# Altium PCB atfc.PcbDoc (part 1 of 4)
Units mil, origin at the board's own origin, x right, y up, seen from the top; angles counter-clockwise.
Board outline 6334.43 x 4147 mil, 6 copper layers (Component Side, Ground Plane (GND), GND/Signal, VCCO/Signal, VCCINT/VCCAUX, Bottom Side), stack 60.473 mil thick; 297 components, 274 nets, 1530 pads, 922 vias.
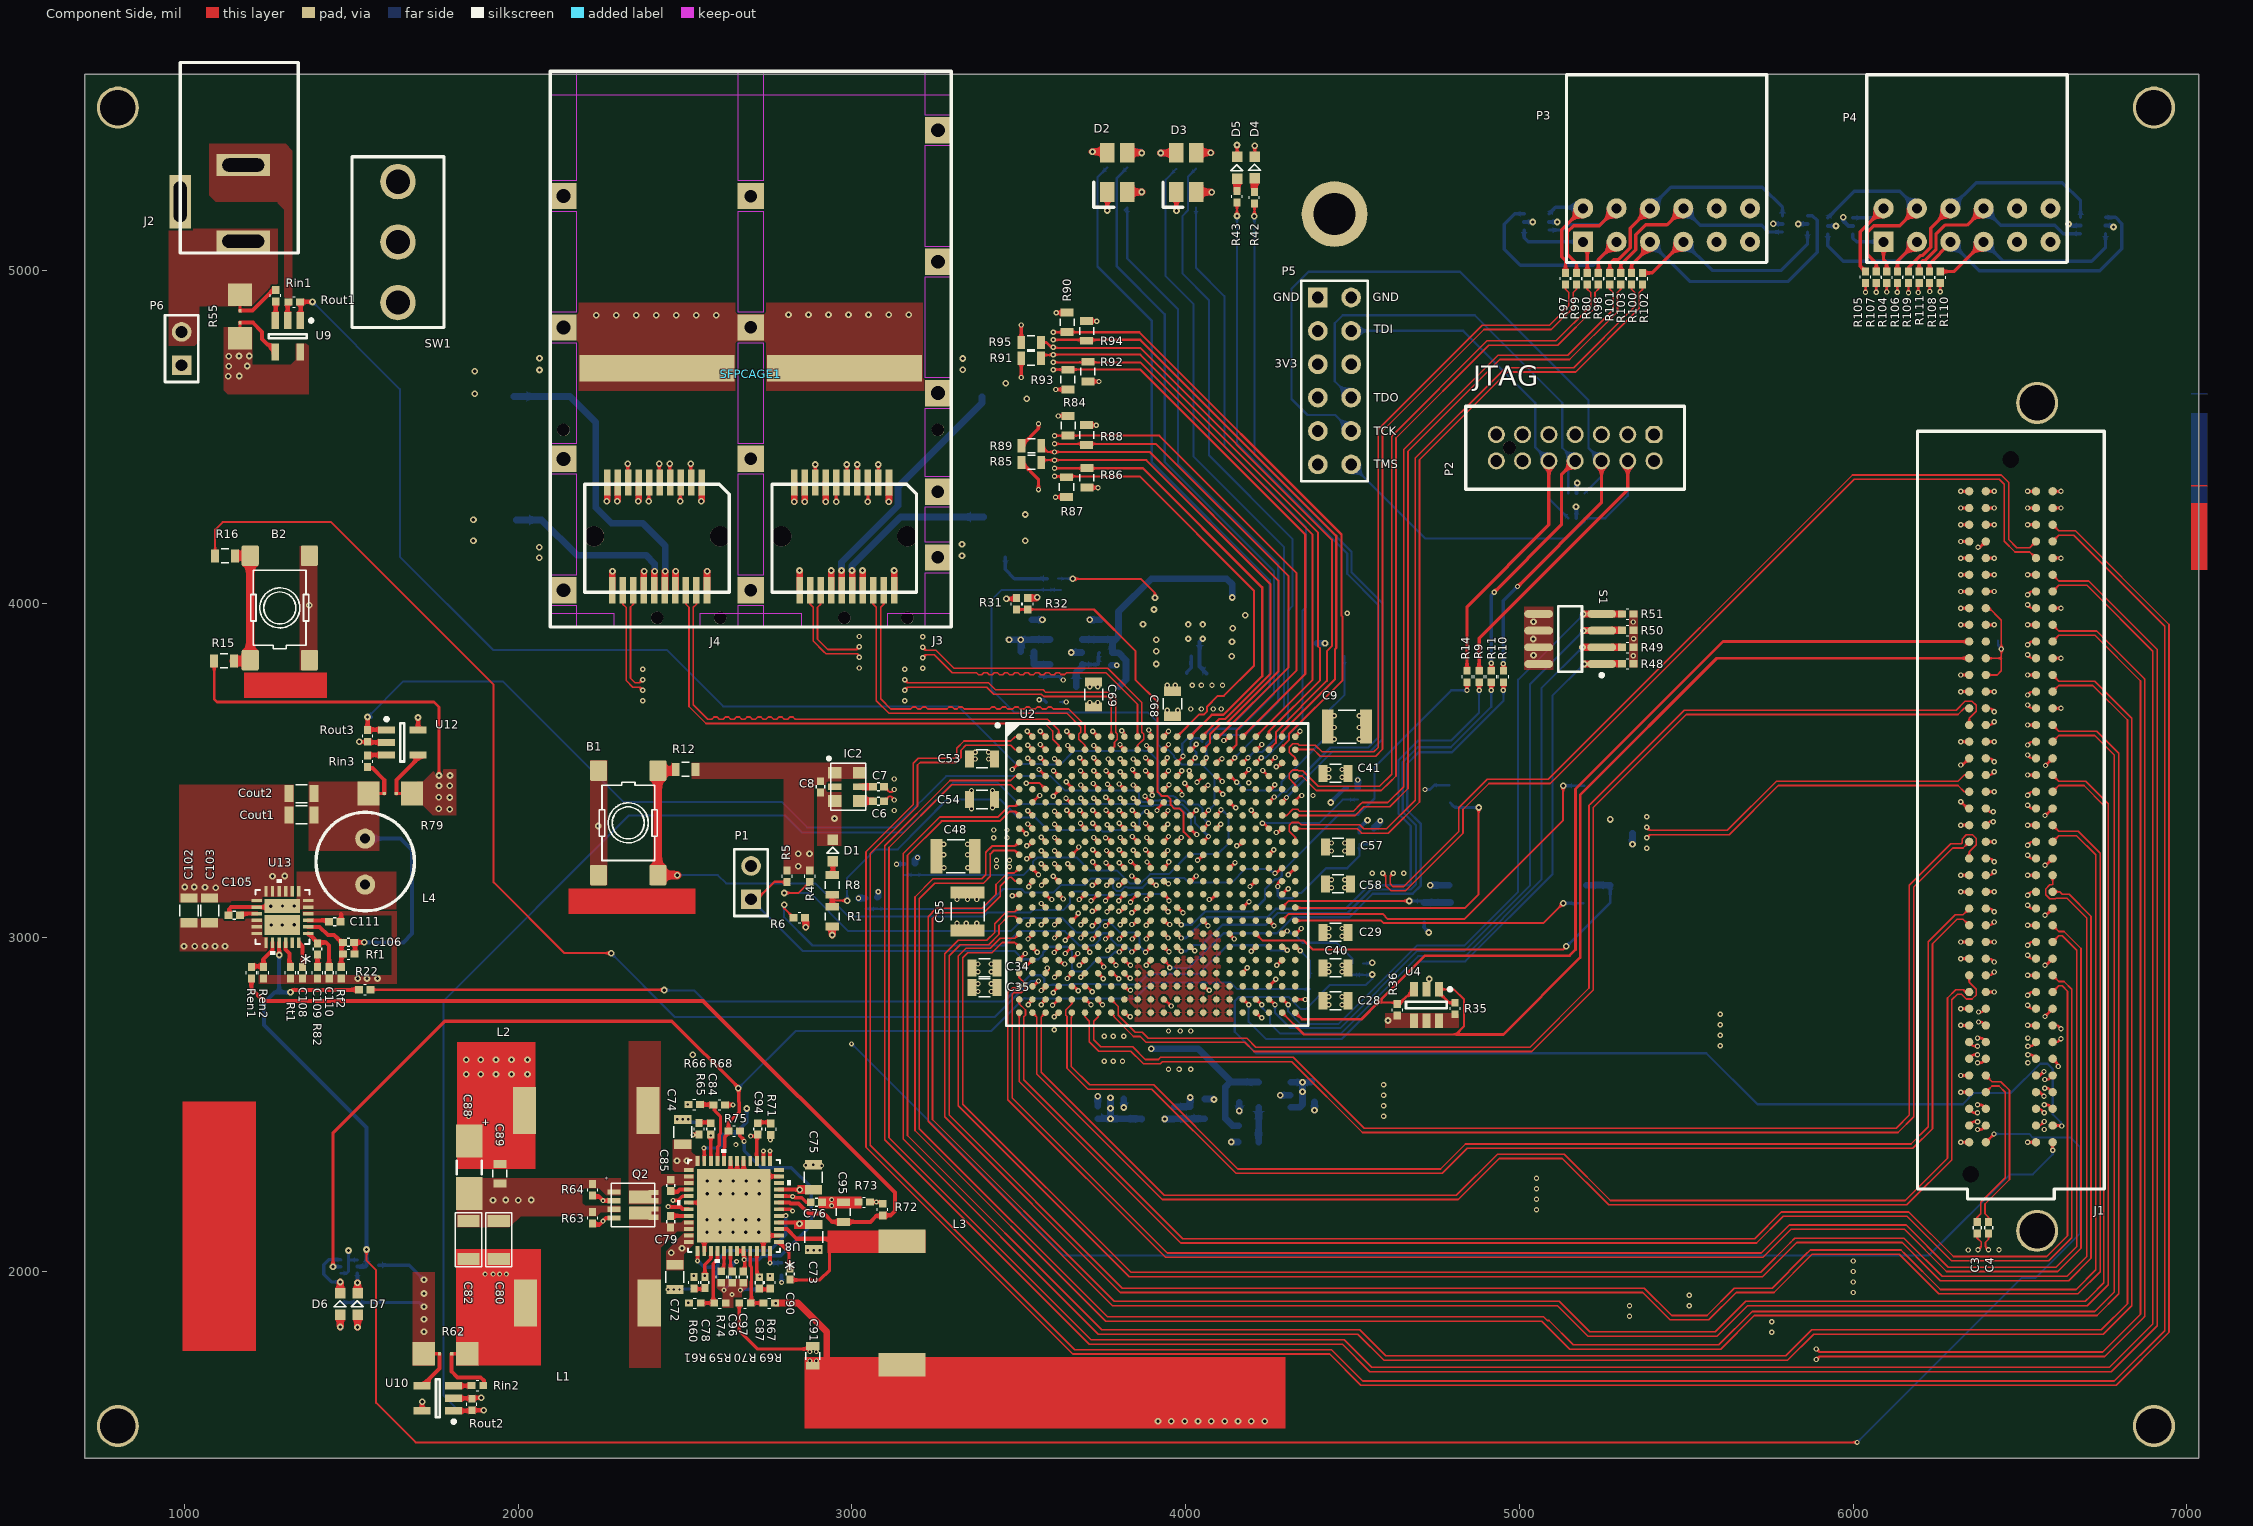
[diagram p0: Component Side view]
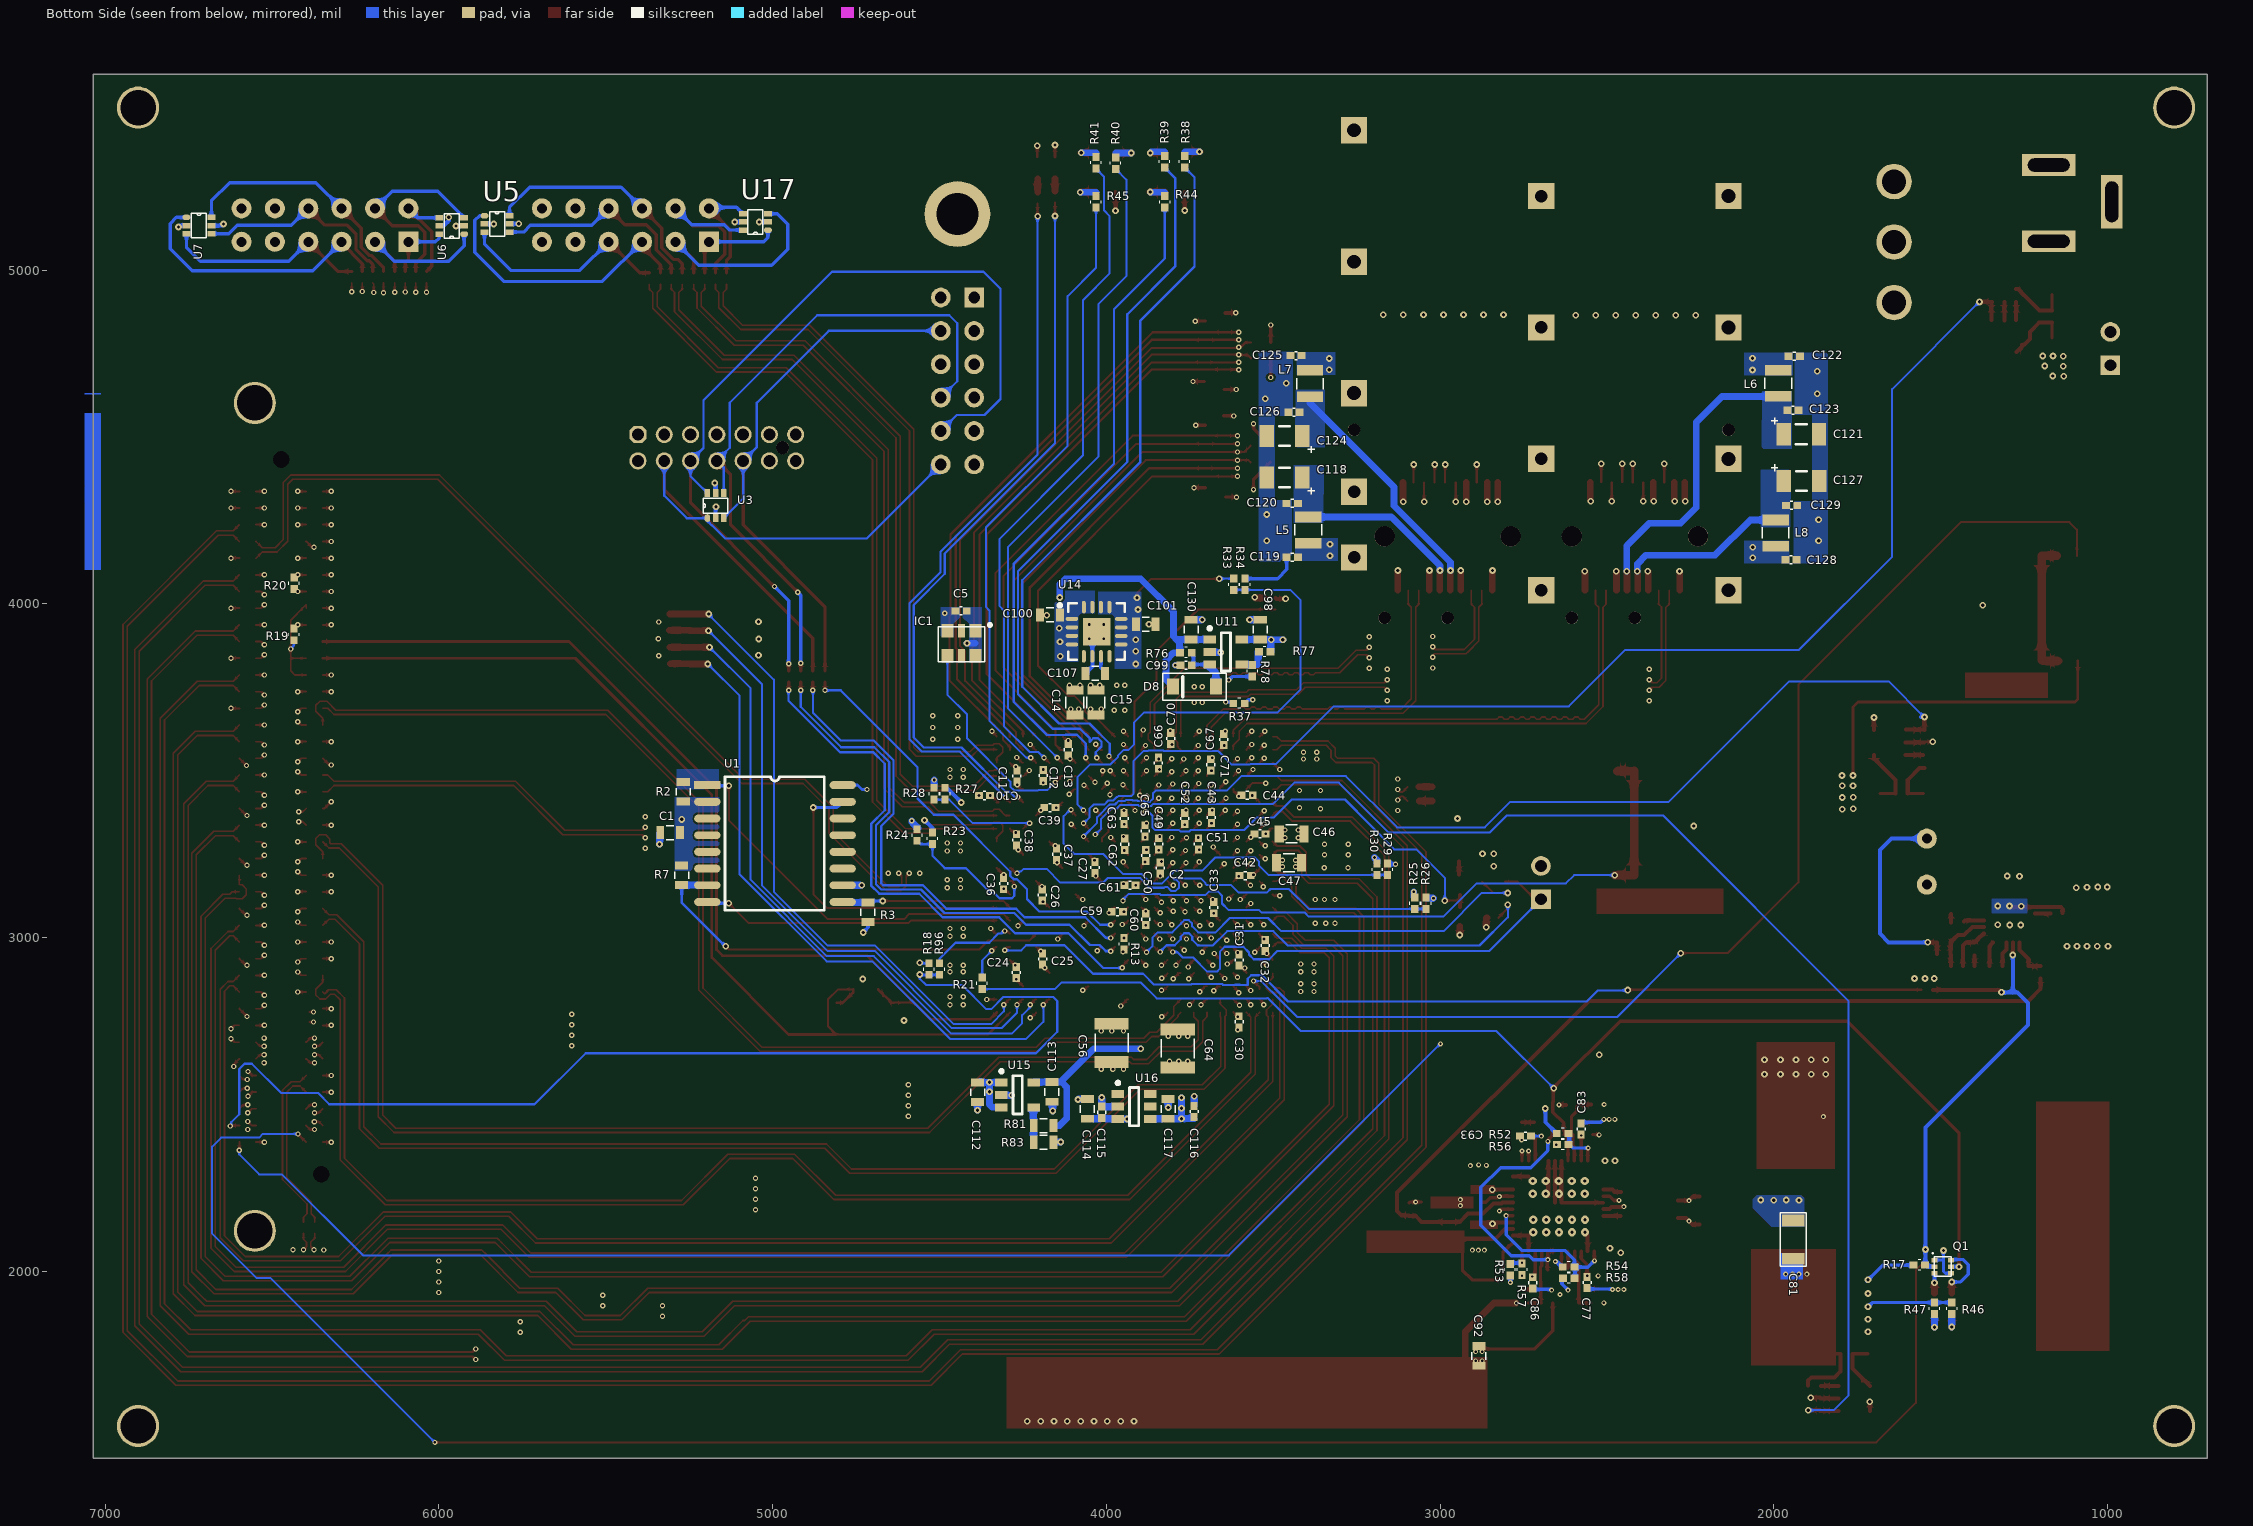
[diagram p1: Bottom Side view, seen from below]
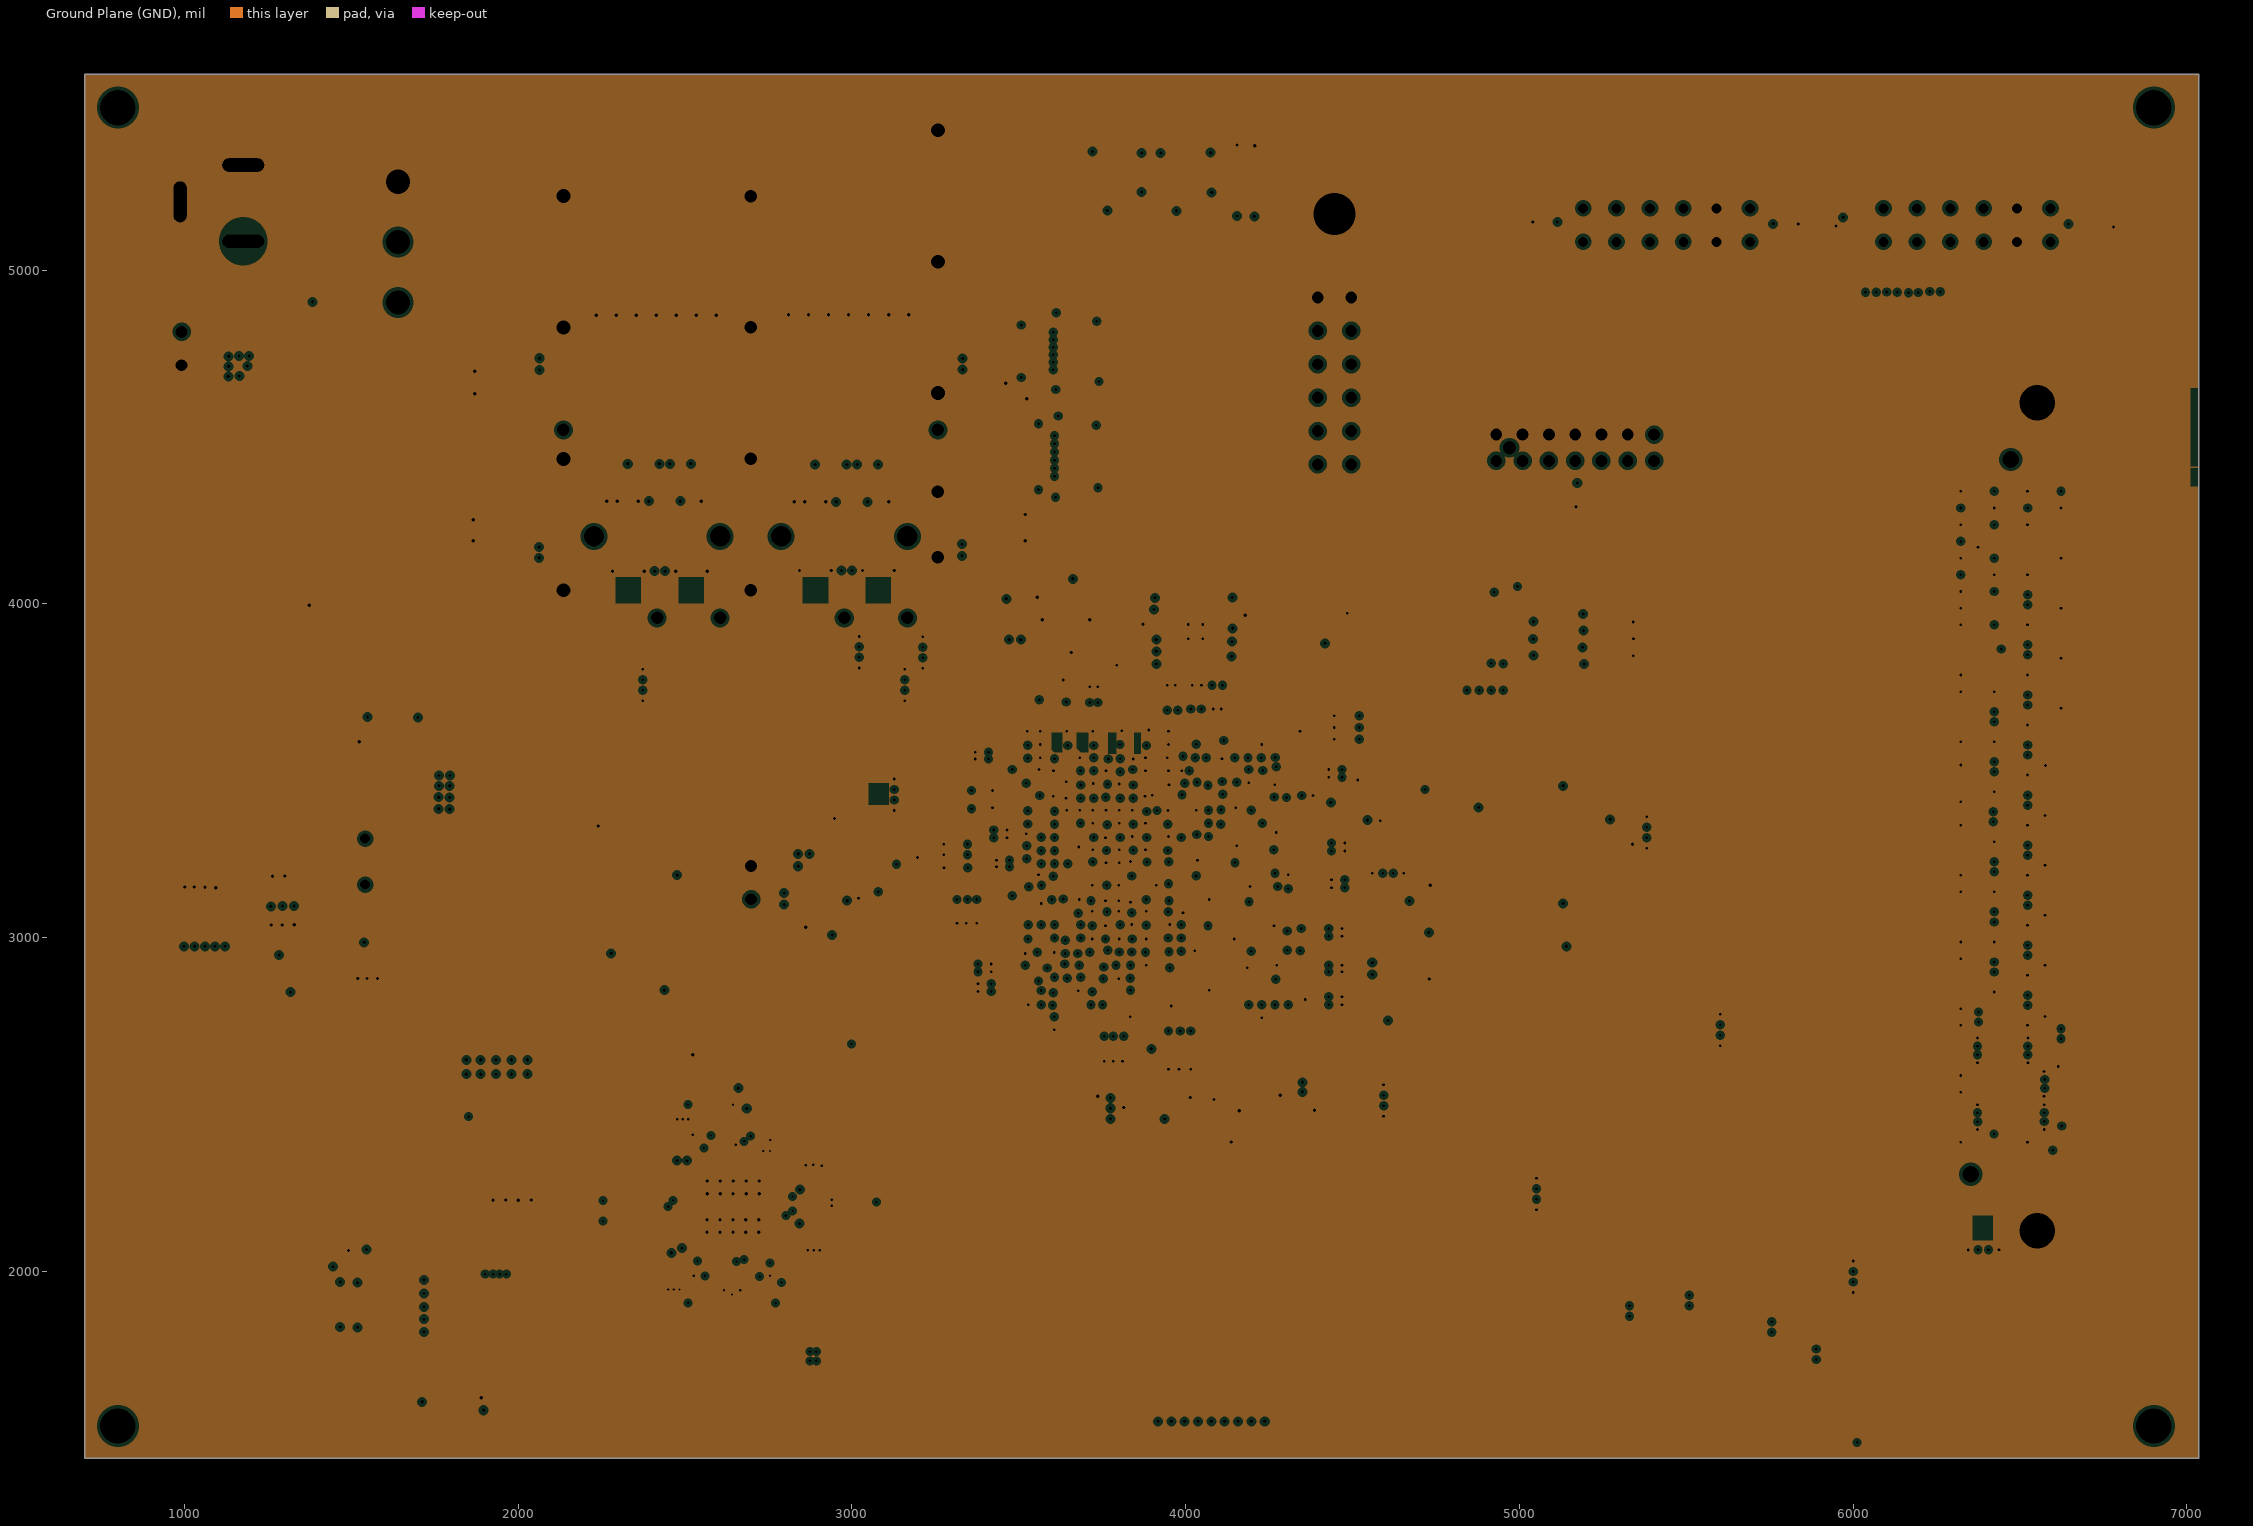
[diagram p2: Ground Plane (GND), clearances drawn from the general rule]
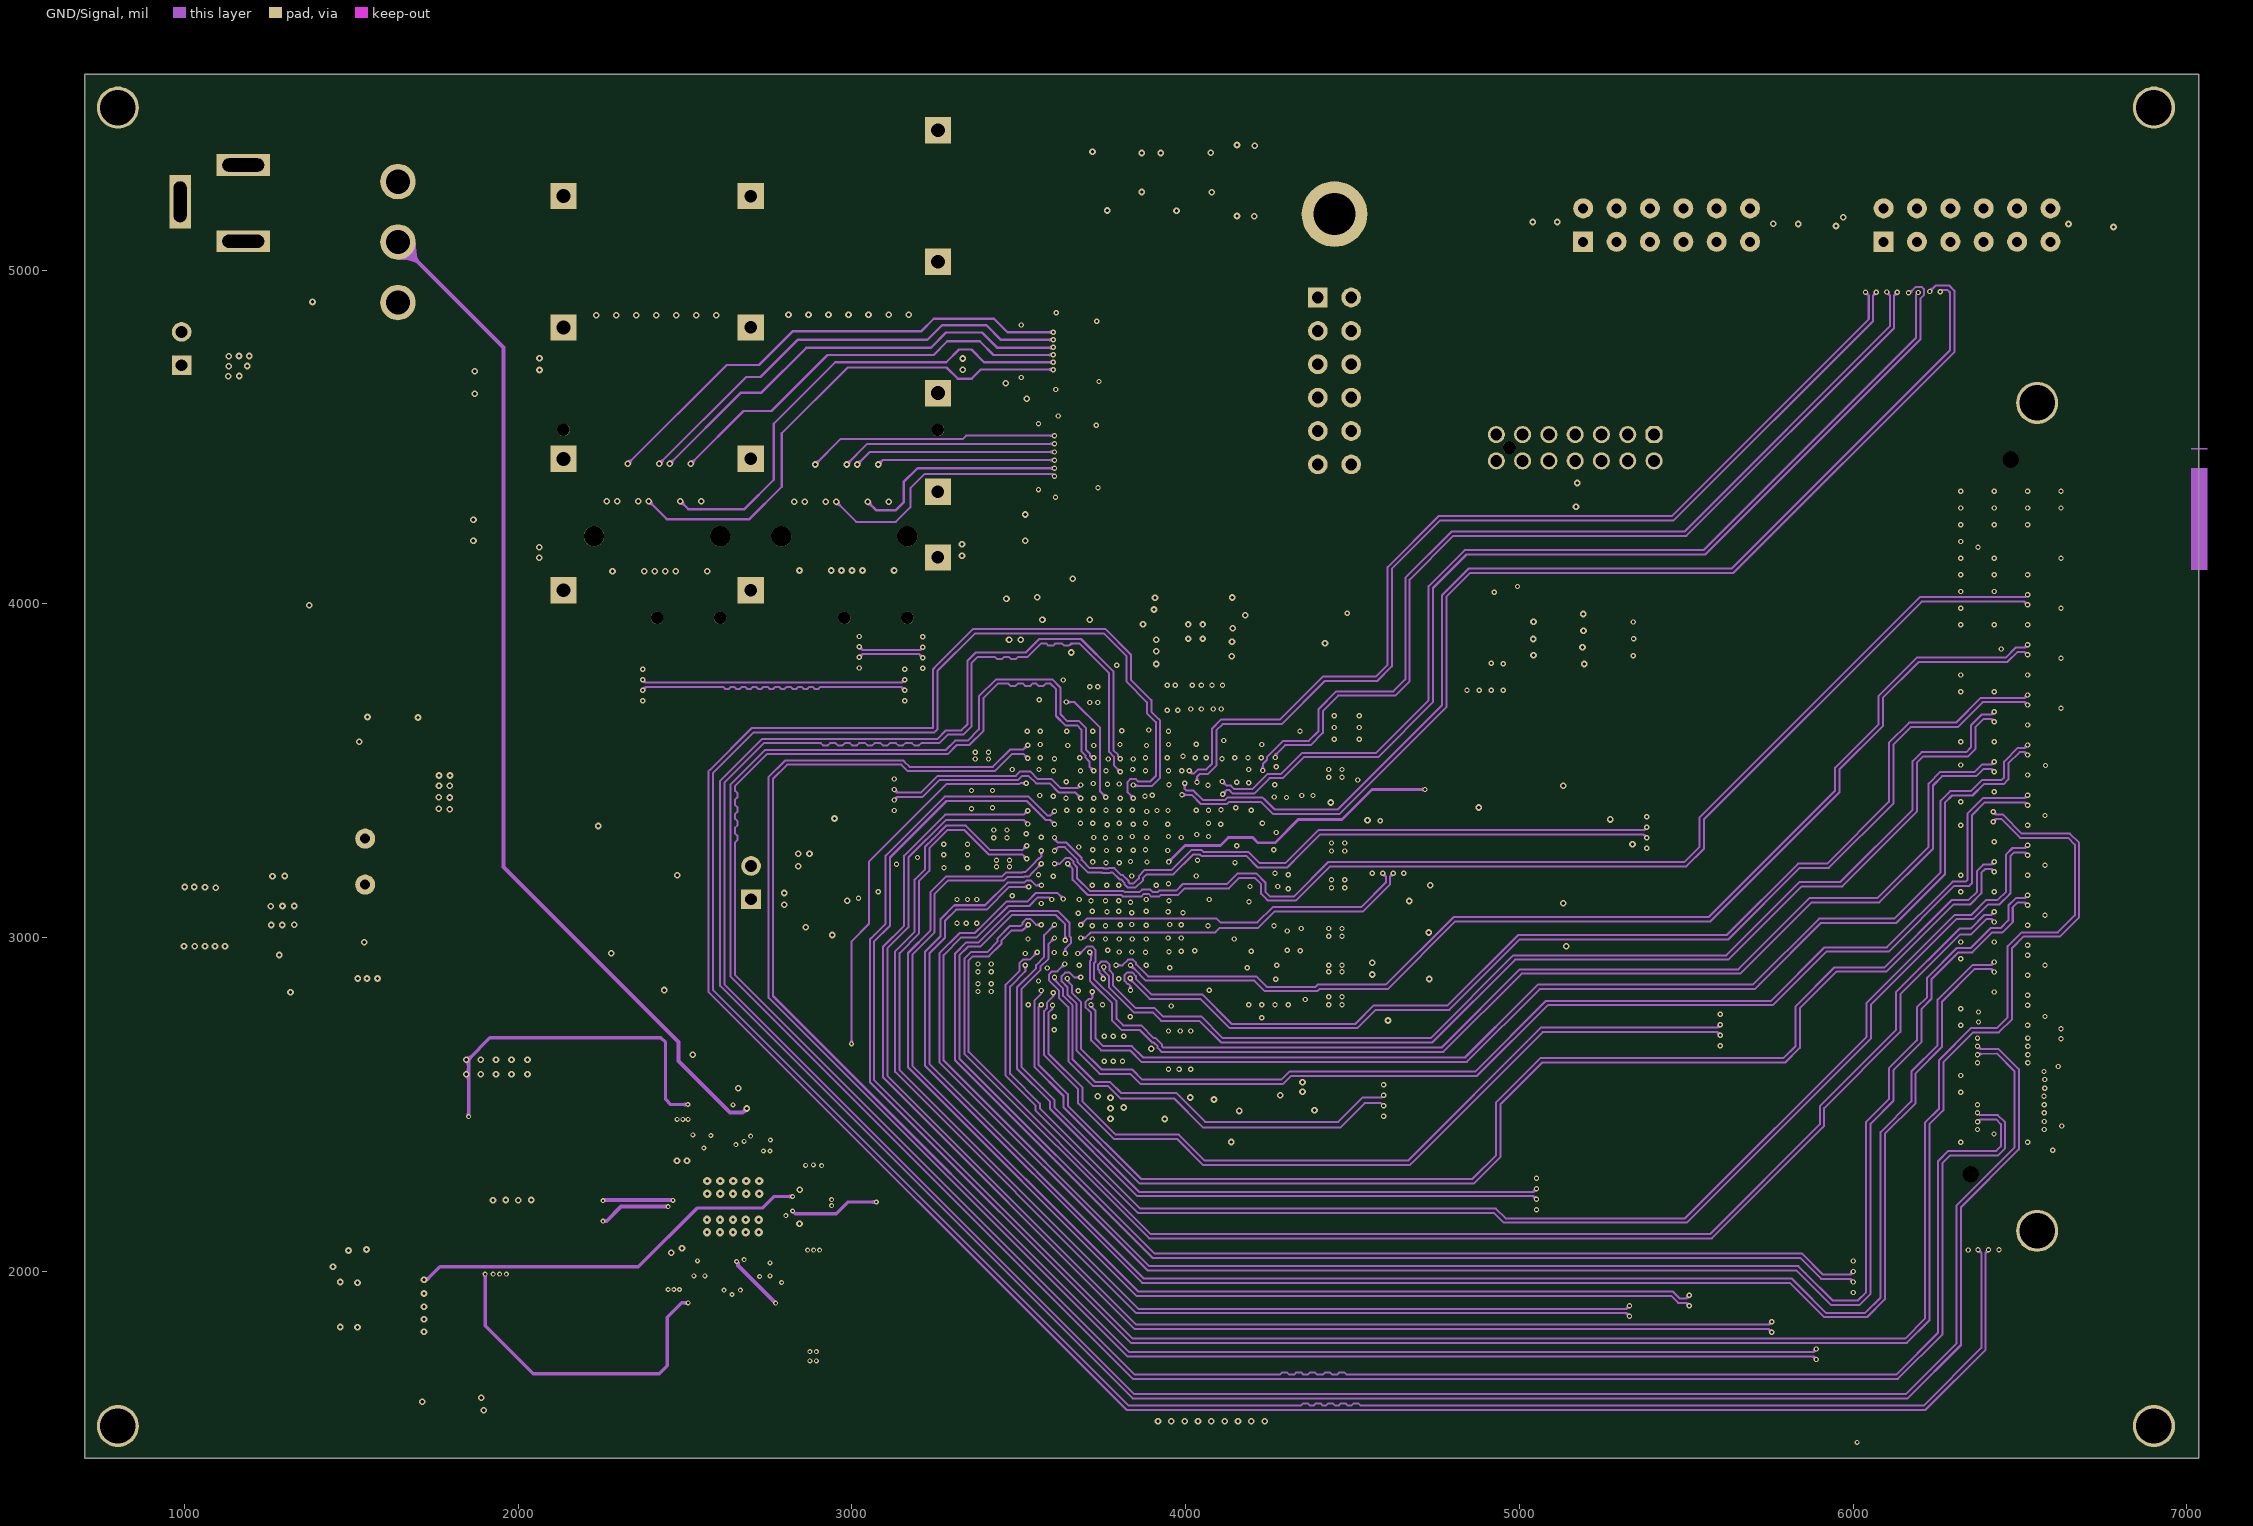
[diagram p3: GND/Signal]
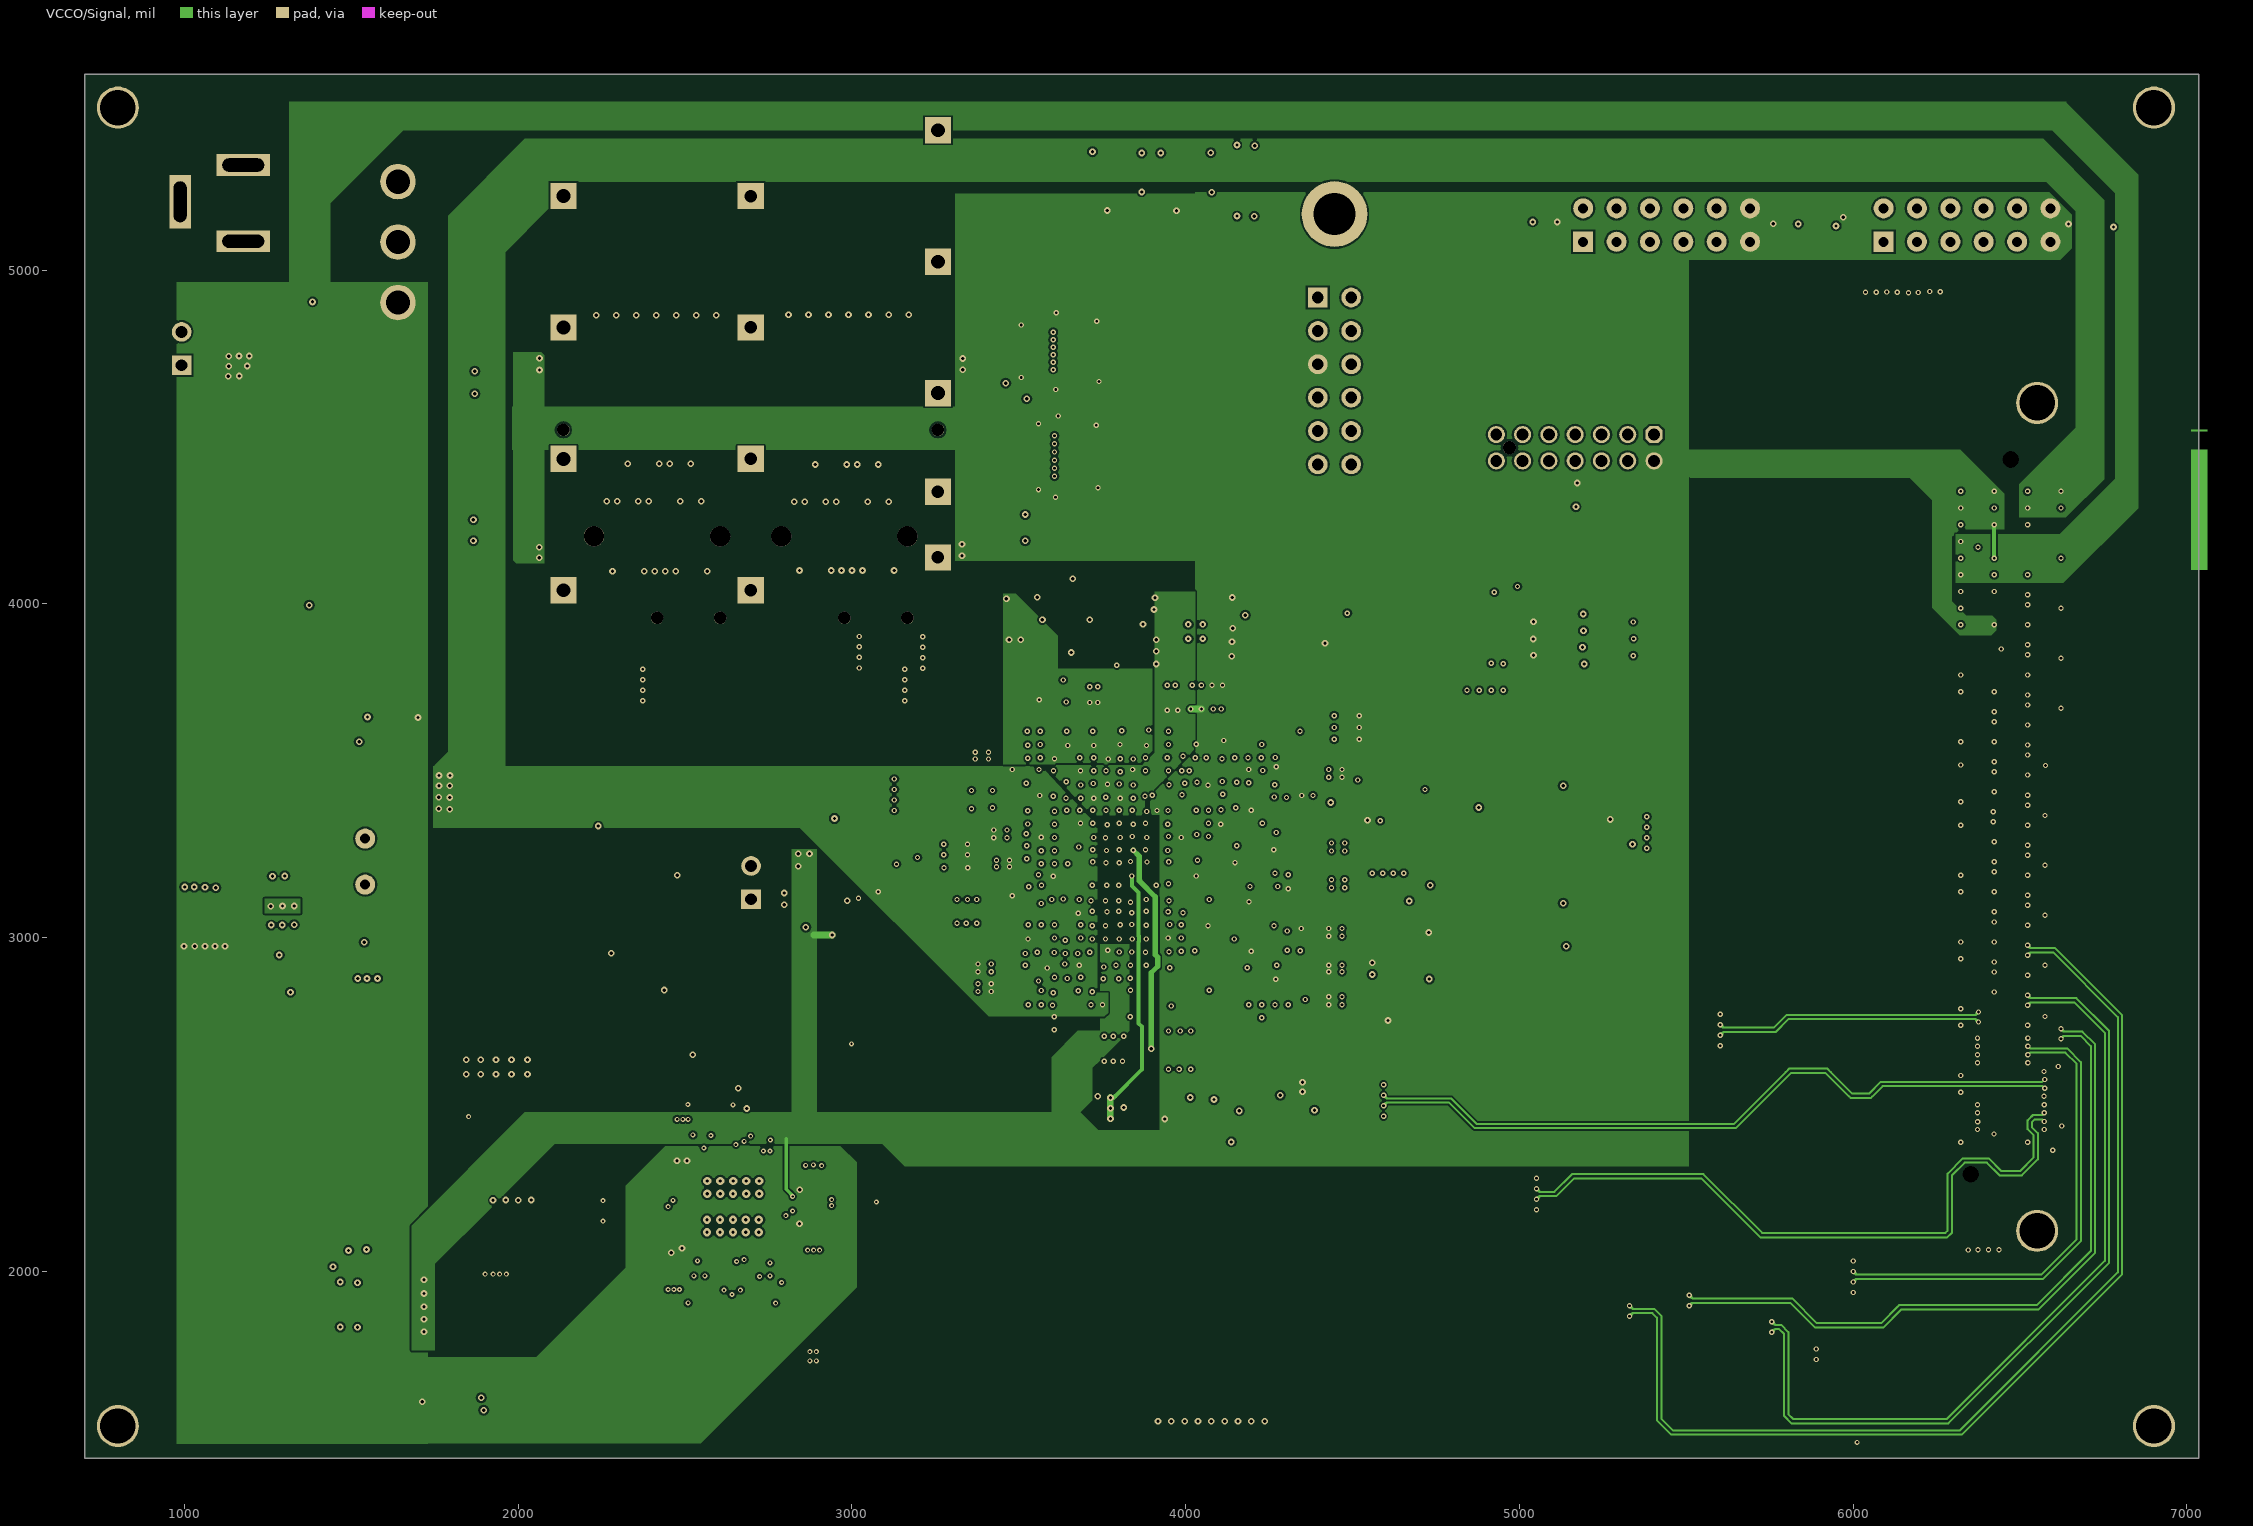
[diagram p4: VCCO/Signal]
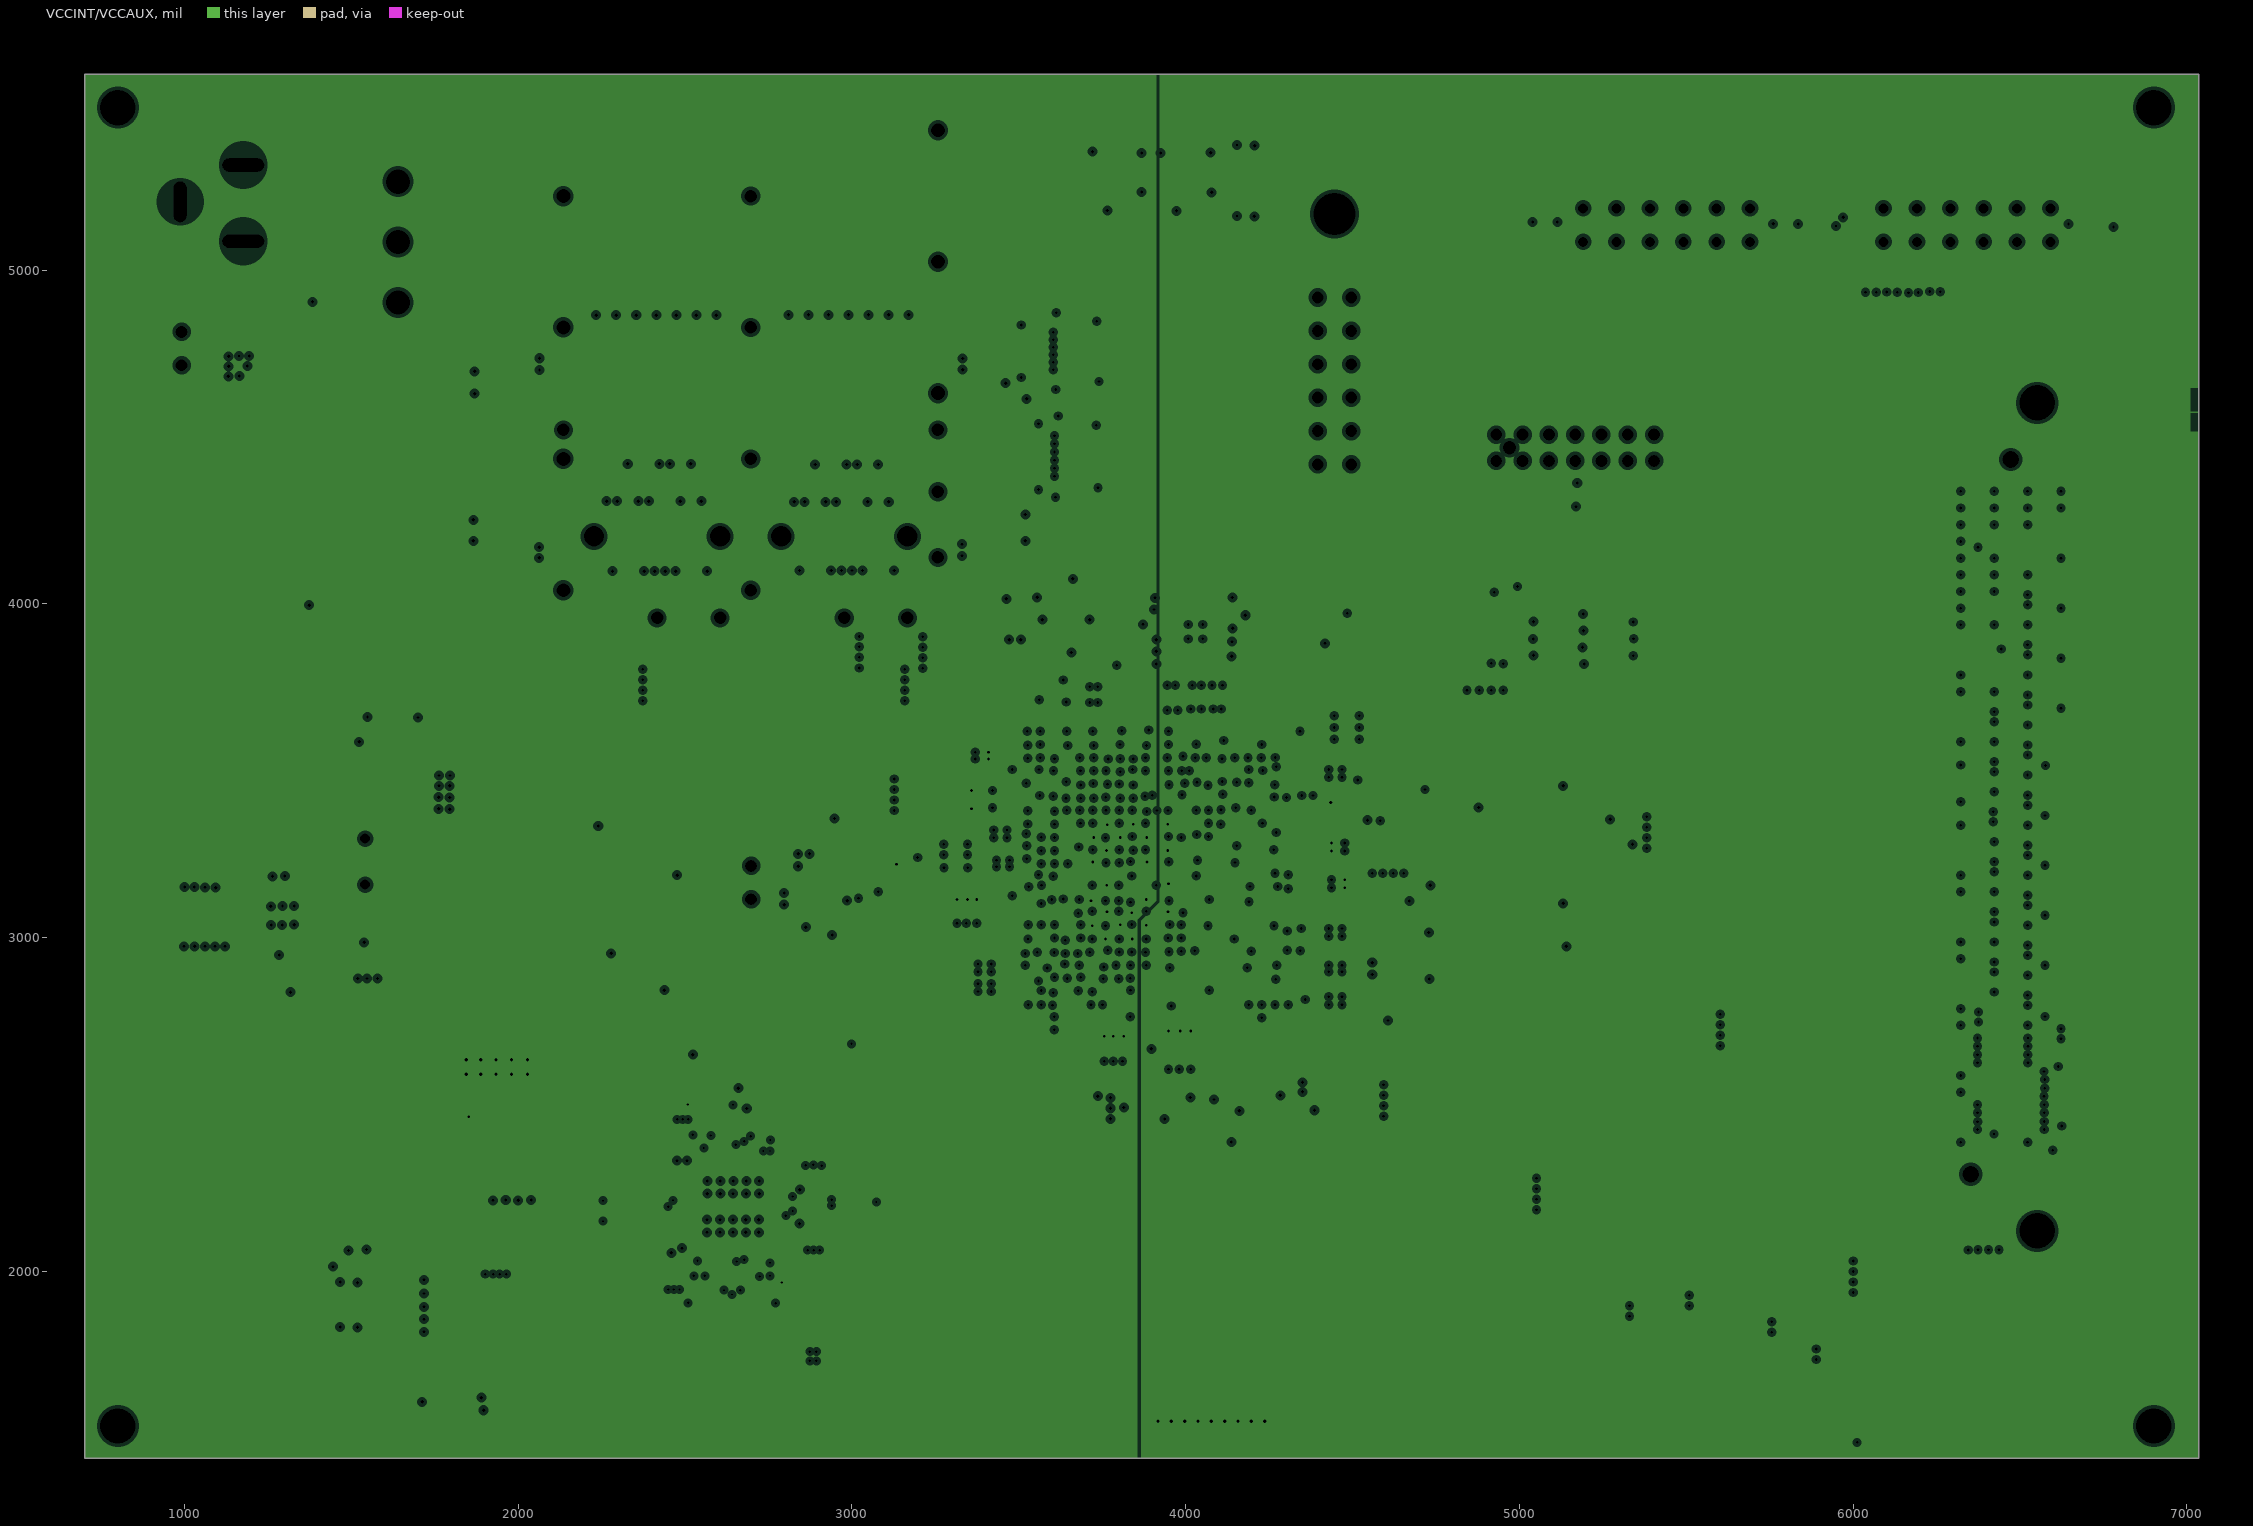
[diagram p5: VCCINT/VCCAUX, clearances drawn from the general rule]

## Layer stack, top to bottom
Top Solder: solder mask 0.9839, Solder Resist, Dk 3.5
Component Side: signal copper 1.378
Prepeg 1: prepreg 4.5276, Dk 4.2
Ground Plane (GND): plane copper 1.378, net GND
Dielectric 10: core 15.748, Dk 4.2
GND/Signal: signal copper 1.378
Dielectric 7: prepreg 11.6535, Dk 4.2
VCCO/Signal: signal copper 1.378
Dielectric 6: core 15.748, Dk 4.2
VCCINT/VCCAUX: plane copper 1.378, net (Multiple Nets)
Dielectric 9: prepreg 4.5276, Dk 4.2
Bottom Side: signal copper 1.378
Bottom Solder: solder mask 0.9839, Solder Resist, Dk 3.5

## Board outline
701,1440 7035.43,1440 7035.43,5587 701,5587
cut-out: 0,0 10,0 10,10 0,10

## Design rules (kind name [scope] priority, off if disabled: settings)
BackDrilling [InAnyDifferentialPair] p1: maxstublength=15 usetopbackdrill=TRUE usebottombackdrill=TRUE holeoversize=1 holetolplus=0 holetolminus=0
Clearance [All] p1: gap=6 ignorepadtopadclearanceinfootprint=FALSE
DiffPairsRouting [All] p1: maxlimit=8 minlimit=5 mostfreqgap=7 toplayer_mingap=8 toplayer_prefgap=8 toplayer_minwidth=5 toplayer_maxwidth=5 toplayer_prefwidth=5 midlayer1_mingap=7 midlayer1_maxgap=7 midlayer1_minwidth=6 midlayer1_maxwidth=6 midlayer1_prefwidth=6 midlayer2_mingap=7 midlayer2_maxgap=7 midlayer2_minwidth=6 midlayer2_maxwidth=6 midlayer2_prefwidth=6 bottomlayer_maxgap=7 bottomlayer_minwidth=5 bottomlayer_maxwidth=6 bottomlayer_prefwidth=6 maxuncoupledlength=130
HoleToHoleClearance [All] p1: gap=5 allowstackedmicrovias=TRUE
Length [All] p1: maxlimit=100000 minlimit=0
MatchedLengths [InAnyDifferentialPair] p1: tolerance=40 checknetsindiffpair=TRUE checkdiffpairvsdiffpair=FALSE checkxsignals=FALSE checkothers=FALSE
MinimumSolderMaskSliver [All] p1: minsoldermaskwidth=1
PlaneClearance [All] p1: clearance=10
PlaneConnect [All] p1: planeconnectstyle=Direct reliefexpansion=20 reliefentries=4 reliefconductorwidth=10 reliefairgap=10
PolygonConnect [InNet('FZ1') vs InNet('FZ1')] p1: connectstyle=Relief reliefconductorwidth=5 reliefentries=4 polygonreliefangle="90 Angle" airgapwidth=5
PolygonConnect PolygonConnect_1 [All] p2: connectstyle=Direct reliefconductorwidth=10 reliefentries=4 polygonreliefangle="90 Angle" airgapwidth=10
RoomDefinition SFP [InComponentClass('SFP')] p1 off: confinementstyle=ConfineIn formatcopy=TRUE lockcomponents=FALSE outline 0,0 2000,0 2000,1000 0,1000
RoomDefinition Regulators [InComponentClass('Regulators')] p2 off: confinementstyle=ConfineIn formatcopy=TRUE lockcomponents=FALSE outline 0,0 2000,0 2000,1000 0,1000
RoomDefinition PWR_APD5052 [InComponentClass('PWR_APD5052')] p3 off: confinementstyle=ConfineIn formatcopy=TRUE lockcomponents=FALSE outline 0,0 2000,0 2000,1000 0,1000
RoomDefinition IO [InComponentClass('IO')] p4 off: confinementstyle=ConfineIn formatcopy=TRUE lockcomponents=FALSE outline 0,0 2000,0 2000,1000 0,1000
RoomDefinition FPGA_PWR [InComponentClass('FPGA_PWR')] p5 off: confinementstyle=ConfineIn formatcopy=TRUE lockcomponents=FALSE outline 0,0 2000,0 2000,1000 0,1000
RoomDefinition FPGA_Banks2 [InComponentClass('FPGA_Banks2')] p6 off: confinementstyle=ConfineIn formatcopy=TRUE lockcomponents=FALSE outline 0,0 2000,0 2000,1000 0,1000
RoomDefinition FPGA_Banks1 [InComponentClass('FPGA_Banks1')] p7 off: confinementstyle=ConfineIn formatcopy=TRUE lockcomponents=FALSE outline 0,0 2000,0 2000,1000 0,1000
RoomDefinition FMC [InComponentClass('FMC')] p8 off: confinementstyle=ConfineIn formatcopy=TRUE lockcomponents=FALSE outline 0,0 2000,0 2000,1000 0,1000
RoomDefinition Config [InComponentClass('Config')] p9 off: confinementstyle=ConfineIn formatcopy=TRUE lockcomponents=FALSE outline 0,0 2000,0 2000,1000 0,1000
RoutingVias [All] p1: holewidth=12 width=23 viastyle="Through Hole" minholewidth=8 minwidth=16 maxholewidth=28 maxwidth=50
SilkToSilkClearance [All] p1: silktosilkclearance=5
SilkToSolderMaskClearance [IsPad] p1 off: minsilkscreentomaskgap=10 clearancetoexposedcopper=TRUE
SolderMaskExpansion [All] p1: expansion=1
ViasUnderSMD [All] p1: allowed=TRUE
Width [All] p1: maxlimit=196.85 minlimit=3.94 preferedwidth=10
23 further rules are at their usual default settings.

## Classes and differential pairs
component class SFP: C118 C119 C120 C121 C122 C123 C124 C125 C126 C127 C128 C129 J3 J4 L5 L6 L7 L8 R84 R85 R86 R87 R88 R89 R90 R91 R92 R93 R94 R95 SFPCAGE1
component class Regulators: C98 C99 C100 C101 C102 C103 C105 C106 C107 C108 C109 C110 C111 C112 C113 C114 C115 C116 C117 C130 Cout1 Cout2 D8 L4 R76 R77 R78 R79 R81 R82 R83 Ren1 Ren2 Rf1 Rf2 Rin3 Rout3 Rt1 U11 U12 U13 U14 U15 U16
component class PWR_APD5052: C72 C73 C74 C75 C76 C77 C78 C79 C80 C81 C82 C83 C84 C85 C86 C87 C88 C89 C90 C91 C92 C93 C94 C95 C96 C97 J2 L1 L2 L3 P6 Q2 R52 R53 R54 R55 R56 R57 R58 R59 R60 R61 R62 R63 R64 R65 R66 R67 R68 R69 R70 R71 R72 R73 R74 R75 Rin1 Rin2 Rout1 Rout2 SW1 U8 U9 U10
component class IO: D2 D3 D4 D5 D6 D7 P3 P4 Q1 R38 R39 R40 R41 R42 R43 R44 R45 R46 R47 R48 R49 R50 R51 R80 R97 R98 R99 R100 R101 R102 R103 R104 R105 R106 R107 R108 R109 R110 R111 S1 U5 U6 U7 U17
component class FPGA_Banks1: R21 R22 R23 R24 R25 R26 R27 R28 R29 R30 R31 R32 R33 R34 R35 R36 R96 U2
component class FMC: C3 C4 J1 R17 R18 R19 R20
component class Config: B1 B2 C1 C2 D1 P1 P2 P5 R1 R2 R3 R4 R5 R6 R7 R8 R9 R10 R11 R12 R13 R14 R15 R16 U1 U3 U4
component class FPGA_Banks2: C5 C6 C7 C8 IC1 IC2 R37
component class FPGA_PWR: C9 C10 C11 C12 C13 C14 C15 C24 C25 C26 C27 C28 C29 C30 C31 C32 C33 C34 C35 C36 C37 C38 C39 C40 C41 C42 C43 C44 C45 C46 C47 C48 C49 C50 C51 C52 C53 C54 C55 C56 C57 C58 C59 C60 C61 C62 C63 C64 C65 C66 C67 C68 C69 C70 C71
differential pair PMODB4: +PMODB4_P -PMODB4_N
differential pair PMODB3: +PMODB3_P -PMODB3_N
differential pair PMODB2: +PMODB2_P -PMODB2_N
differential pair PMODB1: +PMODB1_P -PMODB1_N
differential pair PMODA4: +PMODA4_P -PMODA4_N
differential pair PMODA3: +PMODA3_P -PMODA3_N
differential pair PMODA2: +PMODA2_P -PMODA2_N
differential pair PMODA1: +PMODA1_P -PMODA1_N
differential pair FMC_CLK0_M2C: +FMC_CLK0_M2C_P -FMC_CLK0_M2C_N
differential pair FMC_CLK1_M2C: +FMC_CLK1_M2C_P -FMC_CLK1_M2C_N
differential pair FMC_LA00_CC: +FMC_LA00_CC_P -FMC_LA00_CC_N
differential pair FMC_LA01_CC: +FMC_LA01_CC_P -FMC_LA01_CC_N
differential pair FMC_LA02: +FMC_LA02_P -FMC_LA02_N
differential pair FMC_LA03: +FMC_LA03_P -FMC_LA03_N
differential pair FMC_LA04: +FMC_LA04_P -FMC_LA04_N
differential pair FMC_LA05: +FMC_LA05_P -FMC_LA05_N
differential pair FMC_LA06: +FMC_LA06_P -FMC_LA06_N
differential pair FMC_LA07: +FMC_LA07_P -FMC_LA07_N
differential pair FMC_LA08: +FMC_LA08_P -FMC_LA08_N
differential pair FMC_LA09: +FMC_LA09_P -FMC_LA09_N
differential pair FMC_LA10: +FMC_LA10_P -FMC_LA10_N
differential pair FMC_LA11: +FMC_LA11_P -FMC_LA11_N
differential pair FMC_LA12: +FMC_LA12_P -FMC_LA12_N
differential pair FMC_LA13: +FMC_LA13_P -FMC_LA13_N
differential pair FMC_LA14: +FMC_LA14_P -FMC_LA14_N
differential pair FMC_LA15: +FMC_LA15_P -FMC_LA15_N
differential pair FMC_LA16: +FMC_LA16_P -FMC_LA16_N
differential pair FMC_LA17_CC: +FMC_LA17_CC_P -FMC_LA17_CC_N
differential pair FMC_LA18_CC: +FMC_LA18_CC_P -FMC_LA18_CC_N
differential pair FMC_LA19: +FMC_LA19_P -FMC_LA19_N
differential pair FMC_LA20: +FMC_LA20_P -FMC_LA20_N
differential pair FMC_LA21: +FMC_LA21_P -FMC_LA21_N
differential pair FMC_LA22: +FMC_LA22_P -FMC_LA22_N
differential pair FMC_LA23: +FMC_LA23_P -FMC_LA23_N
differential pair FMC_LA24: +FMC_LA24_P -FMC_LA24_N
differential pair FMC_LA25: +FMC_LA25_P -FMC_LA25_N
differential pair FMC_LA26: +FMC_LA26_P -FMC_LA26_N
differential pair FMC_LA27: +FMC_LA27_P -FMC_LA27_N
differential pair FMC_LA28: +FMC_LA28_P -FMC_LA28_N
differential pair FMC_LA29: +FMC_LA29_P -FMC_LA29_N
differential pair FMC_LA30: +FMC_LA30_P -FMC_LA30_N
differential pair FMC_LA31: +FMC_LA31_P -FMC_LA31_N
differential pair FMC_LA32: +FMC_LA32_P -FMC_LA32_N
differential pair FMC_LA33: +FMC_LA33_P -FMC_LA33_N
differential pair FMC_MGT_C2M: +FMC_MGT_C2M_P -FMC_MGT_C2M_N
differential pair FMC_MGT_CLK: +FMC_MGT_CLK_P -FMC_MGT_CLK_N
differential pair FMC_MGT_M2C: +FMC_MGT_M2C_P -FMC_MGT_M2C_N
differential pair GBTCLK: +GBTCLK_P -GBTCLK_N
differential pair GTP_CLK: +GTP_CLK_P -GTP_CLK_N
differential pair SFP1_RD: +SFP1_RD_P -SFP1_RD_N
differential pair SFP1_TD: +SFP1_TD_P -SFP1_TD_N
differential pair SFP2_RD: +SFP2_RD_P -SFP2_RD_N
differential pair SFP2_TD: +SFP2_TD_P -SFP2_TD_N

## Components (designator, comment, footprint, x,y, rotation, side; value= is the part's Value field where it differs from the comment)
B1 "B3S-1002" B3S-1002 2330,3344 r270 top
B2 "B3S-1002" B3S-1002 1286,3988 r90 top
C1 "Cap" C0603 5307.09,3314.96 r180 bottom value=100nF
C2 "Cap" C0402 3838.58,3208.66 r270 bottom value=100nF
C3 "Cap" C0402 6371.51,2130.91 r270 top value=100nF
C4 "Cap" C0402 6405.51,2130.91 r270 top value=100nF
C5 "Cap" C0402 4435,3979 r180 bottom value=10nF
C6 "Cap" C0402 3080,3409 r0 top value=100nF
C7 "Cap" C0402 3080,3452 r0 top value=100nF
C8 "Cap" C0402 2906,3452 r90 top value=10nF
C9 "Cap" C1210 4483,3633 r180 top value=47uF
C10 "Cap" C0402 4365,3426 r0 bottom value=0.47uF
C11 "Cap" C0402 4267.72,3484.25 r270 bottom value=0.47uF
C12 "Cap" C0402 4189,3486 r270 bottom value=0.47uF
C13 "Cap" C0402 4114.17,3562.99 r270 bottom value=0.47uF
C14 "Cap" C0805 4094.49,3704.72 r270 bottom value=4.7uF
C15 "Cap" C0805 4031.5,3704.72 r90 bottom value=4.7uF
C24 "Cap" C0402 4270,2896 r90 bottom value=0.47uF
C25 "Cap" C0402 4191,2936 r270 bottom value=0.47uF
C26 "Cap" C0402 4192,3128 r90 bottom value=0.47uF
C27 "Cap" C0402 4034,3210 r90 bottom value=0.47uF
C28 "Cap" C0805 4448.82,2811.02 r0 top value=4.7uF
C29 "Cap" C0805 4448.82,3015.75 r0 top value=4.7uF
C30 "Cap" C0402 3602.36,2748.03 r270 bottom value=0.47uF
C31 "Cap" C0402 3602.36,2933.07 r90 bottom value=0.47uF
C32 "Cap" C0402 3523.62,2976.38 r270 bottom value=0.47uF
C33 "Cap" C0402 3678,3090 r90 bottom value=0.47uF
C34 "Cap" C0805 3397.64,2909.45 r0 top value=4.7uF
C35 "Cap" C0805 3397.64,2850.39 r180 top value=4.7uF
C36 "Cap" C0402 4308,3162 r90 bottom value=0.47uF
C37 "Cap" C0402 4149,3250 r90 bottom value=0.47uF
C38 "Cap" C0402 4269,3293 r90 bottom value=0.47uF
C39 "Cap" C0402 4169.29,3389.76 r180 bottom value=0.47uF
C40 "Cap" C0805 4448.82,2909.45 r0 top value=4.7uF
C41 "Cap" C0805 4448.82,3492.13 r180 top value=4.7uF
C42 "Cap" C0402 3584,3186 r180 bottom value=0.47uF
C43 "Cap" C0402 3685,3360 r90 bottom value=0.47uF
C44 "Cap" C0402 3578,3427 r0 bottom value=0.47uF
C45 "Cap" C0402 3539.37,3311.02 r180 bottom value=0.47uF
C46 "Cap" C0805 3444.88,3311.02 r0 bottom value=4.7uF
C47 "Cap" C0805 3452.76,3224.41 r180 bottom value=4.7uF
C48 "Cap" C1210 3311.02,3244.09 r180 top value=47uF
C49 "Cap" C0402 3843,3281 r270 bottom value=100nF
C50 "Cap" C0402 3882,3246 r90 bottom value=0.47uF
C51 "Cap" C0402 3724,3281 r270 bottom value=0.47uF
C52 "Cap" C0402 3765,3357 r90 bottom value=0.47uF
C53 "Cap" C0805 3389.76,3535.43 r180 top value=4.7uF
C54 "Cap" C0805 3389.76,3414 r0 top value=4.7uF
C55 "Cap" C1210 3346.46,3078.74 r270 top value=100uF
C56 "Cap" C1210 3984.25,2685.04 r270 bottom value=47uF
C57 "Cap" C0805 4456.69,3271.65 r0 top value=4.7uF
C58 "Cap" C0805 4456.69,3161.42 r180 top value=4.7uF
C59 "Cap" C0402 3967,3078 r0 bottom value=0.47uF
C60 "Cap" C0402 3881.89,3055.12 r90 bottom value=0.47uF
C61 "Cap" C0402 3929,3157 r180 bottom value=0.47uF
C62 "Cap" C0402 3945,3280 r90 bottom value=0.47uF
C63 "Cap" C0402 3947,3357 r90 bottom value=0.47uF
C64 "Cap" C1210 3786,2668 r270 bottom value=47uF
C65 "Cap" C0402 3884,3320 r90 bottom value=0.47uF
C66 "Cap" C0402 3844,3523 r90 bottom value=100nF
C67 "Cap" C0402 3687,3518 r90 bottom value=100nF
C68 "Cap" C0805 3960.63,3700.79 r90 top value=4.7uF
C69 "Cap" C0805 3724.41,3728.35 r270 top value=4.7uF
C70 "Cap" C0402 3807,3597 r270 bottom value=100nF
C71 "Cap" C0402 3648,3594 r270 bottom value=100nF
C72 "" C0805 2469.68,1983 r90 top value=10uF
C73 "" C0805 2885.68,2103 r90 top value=10uF
C74 "Cap" C0805 2493.31,2418.28 r270 top value=10uF
C75 "Cap" C0805 2884.63,2282.28 r270 top value=10uF
C76 "" C0402 2893.63,2207.28 r180 top value=1uF
C77 "No Load" C0402 2559.68,1967 r90 bottom value=0
C78 "Cap" C0402 2559.68,1967 r90 top value=1.8nF
C79 "Cap" C0402 2456.68,2149 r270 top value=100nF
C80 "GRM31CR60J107ME39" C1206 1942.31,2094.28 r270 top value=100uF
C81 "GRM31CR60J107ME39" C1206 1942.31,2095.28 r270 bottom value=100uF
C82 "GRM31CR60J107ME39" C1206 1851.31,2094.28 r270 top value=100uF
C83 "No Load" C0402 2577.68,2427 r270 bottom value=0
C84 "Cap" C0402 2577.31,2427.28 r270 top value=1.8nF
C85 "Cap" C0402 2457.68,2258 r270 top value=100nF
C86 "No Load" C0402 2722.68,1966 r90 bottom value=0
C87 "Cap" C0402 2722.68,1966 r90 top value=2.2nF
C88 "T491X687K006AT" C7343 1853.68,2312 r270 top value=680uF
C89 "Cap" C0603 1945.68,2293 r90 top value=10uF
C90 "Cap" C0402 2814.96,1992.13 r90 top value=100nF
C91 "GRM188R60J226MEA0" C0603 2882.68,1747 r270 top value=22uF
C92 "GRM188R60J226MEA0" C0603 2883.68,1747 r270 bottom value=22uF
C93 "No Load" C0402 2744.09,2405.51 r180 bottom value=0
C94 "Cap" C0402 2718.31,2427.28 r270 top value=2.2nF
C95 "Cap" C0603 2974.68,2178 r270 top value=22uF
C96 "Cap" C0402 2641.68,1983 r90 top value=1uF
C97 "Cap" C0402 2674.68,1983 r90 top value=1uF
C98 "" C0603 3539,3923 r90 bottom value=1uF
C99 "" C0402 3761,3816 r0 bottom value=0.1uF
C100 "" C0603 4168.91,3966.8 r0 bottom value=4.7uF
C101 "" C0603 3882,3939 r180 bottom value=4.7uF
C102 "" C0805 1014,3081.9 r90 top value=10uF
C103 "" C0805 1076,3081.9 r90 top value=10uF
C105 "Cap" C0402 1149.61,3066.93 r0 top value=100nF
C106 "" C0402 1492,2985.9 r180 top value=15pF
C107 "" C0603 4033.12,3792 r0 bottom value=10nF
C108 "" C0402 1354,2894.9 r270 top value=56nF
C109 "" C0402 1399,2965.9 r270 top value=1.2nF
C110 "" C0402 1434,2894.9 r270 top value=15pF
C111 "" C0402 1450.68,3047.9 r180 top value=1uF
C112 "" C0603 4386,2537 r270 bottom value=1uF
C113 "" C0603 4163,2538 r270 bottom value=1uF
C114 "" C0603 4057,2487 r90 bottom value=1uF
C115 "" C0402 4014,2477 r90 bottom value=0.1uF
C116 "" C0402 3737,2479 r90 bottom value=0.1uF
C117 "" C0603 3815,2487 r90 bottom value=10uF
C118 "" C1206_P 3466,4378.6 r0 bottom value=22uF
C119 "Cap" C0402 3443,4140 r180 bottom value=100nF
C120 "Cap" C0402 3443,4301 r180 bottom value=100nF
C121 "" C1206_P 1918,4508.4 r180 bottom value=22uF
C122 "Cap" C0402 1939,4742 r0 bottom value=100nF
C123 "Cap" C0402 1943,4580 r0 bottom value=100nF
C124 "" C1206_P 3466,4503 r0 bottom value=22uF
C125 "Cap" C0402 3432,4744 r180 bottom value=100nF
C126 "Cap" C0402 3438,4574 r180 bottom value=100nF
C127 "" C1206_P 1917.85,4368 r180 bottom value=22uF
C128 "Cap" C0402 1948.85,4132.03 r0 bottom value=100nF
C129 "Cap" C0402 1946.85,4295.03 r0 bottom value=100nF
C130 "" C0603 3746,3923 r270 bottom value=1uF
Cout1 "Cap" C0805 1351,3367.9 r0 top value=10uF
Cout2 "Cap" C0805 1351,3431.9 r0 top value=10uF
D1 "KPT-1608EC" KP-1608QBC-D 2943,3261 r90 top
D2 "ASMB-MTB0-0A3A2" ASMB-MTB0-0A3A2 3795,5293 r0 top
D3 "ASMB-MTB0-0A3A2" ASMB-MTB0-0A3A2 4002,5293 r0 top
D4 "KPT-1608EC" KP-1608QBC-D 4207,5307.52 r90 top
D5 "KPT-1608EC" KP-1608QBC-D 4154,5306.52 r90 top
D6 "KPT-1608EC" KP-1608QBC-D 1467,1902.52 r90 top
D7 "KPT-1608EC" KP-1608QBC-D 1519,1902.52 r90 top
D8 "MBR0530" SOD-123 3736.22,3751.97 r180 bottom
IC1 "DSC1123CI5-100.0000" DSC1123_32_25 4434,3882 r0 bottom
IC2 "DSC1123CE1-125.0000" DSC1123_32_25 2986,3452 r270 top
J1 "ASP-134603-01" ASP-134603-01 6472.44,3362.2 r270 top locked
J2 "PWR2.5" KLD2020 1082,5622 r270 top
J3 "74441-0001" SFP+20 3166.27,4202.3 r180 top
J4 "74441-0001" SFP+20 2605.24,4202.3 r180 top
L1 "MSS1048-332NL" MSS1048 2207.31,1905.28 r270 top value=3.3uH
L2 "MSS1048-152NL" MSS1048 2204.31,2482.28 r270 top value=1.5uH
L3 "MSS1048-472NL" MSS1048 3150.28,1905.28 r0 top value=4.7uH
L4 "DR0608-332L" DR0608 1542,3227.9 r90 top value=3.3uH
L5 "SRP2512-4R7M" SRP2512 3395,4221 r90 bottom value=4.7uH
L6 "SRP2512-4R7M" SRP2512 1987,4661 r270 bottom value=4.7uH
L7 "SRP2512-4R7M" SRP2512 3390,4660 r270 bottom value=4.7uH
L8 "SRP2512-4R7M" SRP2512 1994.85,4212.03 r90 bottom value=4.7uH
P1 "Jumper" HDR1X2 2698,3115 r90 top
P2 "87831-1420" 87831-1420 5167,4468 r180 top
P3 "PMOD" PMOD_12 5441,5135 r90 top
P4 "PMOD" PMOD_12 6341,5135 r90 top
P5 "XMOD" HDR2X6 4396,4918 r270 top
P6 "Header 2" HDR1X2 992,4715 r90 top
Q1 "EM6K6T2R" SOT-563 1494,2014.52 r270 bottom
Q2 "SI7232DN-T1-GE3" 1212-8dual 2344.31,2199.28 r0 top
R1 "Res" R0603 2941,3063 r270 top value=200
R2 "Res" R0603 5267.72,3437.01 r270 bottom value=4k7
R3 "Res" R0603 4714.35,3076 r270 bottom value=4k7
R4 "Res" R0402 2874,3184 r90 top value=1k
R5 "Res" R0402 2806,3184 r90 top value=1k
R6 "Res" R0402 2843,3060 r180 top value=1k
R7 "Res" R0603 5272.35,3187 r90 bottom value=4k7
R8 "Res" R0603 2941,3158 r270 top value=100
R9 "Res" R0402 4879.33,3782 r90 top value=100
R10 "Res" R0402 4952,3782 r90 top value=100
R11 "Res" R0402 4915.67,3782 r90 top value=100
R12 "Res" R0603 2502,3504 r0 top value=4k7
R13 "Res" R0402 3947,2981 r90 bottom value=4k7
R14 "Res" R0402 4843,3782 r90 top value=100
R15 "Res" R0603 1119,3829 r180 top value=10k
R16 "Res" R0603 1122,4144 r0 top value=10k
R17 "Res" R0402 1564,2019 r0 bottom value=10k
R18 "Res" R0402 4531.5,2905.51 r90 bottom value=10k
R19 "Res" R0402 6434,3908 r90 bottom value=10k
R20 "Res" R0402 6433,4062 r270 bottom value=10k
R21 "Res" R0402 4372,2863.73 r270 bottom value=10k
R22 "Res" R0402 1541,2844 r180 top value=10k
R23 "Res" R0402 4521,3297 r90 bottom value=10k
R24 "Res" R0402 4566.93,3307.09 r90 bottom value=22k
R25 "Res" R0402 3076,3103 r90 bottom value=10k
R26 "Res" R0402 3042,3103 r90 bottom value=22k
R27 "Res" R0402 4483,3431.27 r90 bottom value=10k
R28 "Res" R0402 4516,3431.27 r90 bottom value=22k
R29 "Res" R0402 3157.48,3204.72 r90 bottom value=10k
R30 "Res" R0402 3188.98,3204.72 r90 bottom value=22k
R31 "Res" R0402 3493,4000 r90 top value=10k
R32 "Res" R0402 3527,4000 r90 top value=22k
R33 "Res" R0402 3618,4058 r90 bottom value=10k
R34 "Res" R0402 3585,4058 r90 bottom value=22k
R35 "Res" R0402 4807.09,2787.4 r90 top value=10k
R36 "Res" R0402 4633.86,2783.46 r90 top value=10k
R37 "Res" R0402 3602,3702 r0 bottom value=100
R38 "Res" R0402 3765,5325 r270 bottom value=150
R39 "Res" R0402 3825,5325 r270 bottom value=150
R40 "Res" R0402 3972,5321 r270 bottom value=150
R41 "Res" R0402 4031,5322 r270 bottom value=150
R42 "Res" R0402 4206,5217.31 r270 top value=100
R43 "Res" R0402 4154,5220.52 r270 top value=100
R44 "Res" R0402 3825,5204 r90 bottom value=150
R45 "Res" R0402 4031,5204 r90 bottom value=150
R46 "Res" R0402 1467,1889 r90 bottom value=100
R47 "Res" R0402 1519,1889 r90 bottom value=100
R48 "Res" R0402 5324,3821 r0 top value=10k
R49 "Res" R0402 5324,3870 r0 top value=10k
R50 "Res" R0402 5324,3921 r0 top value=10k
R51 "Res" R0402 5324,3970 r0 top value=10k
R52 "Res" R0402 2632.68,2413 r0 bottom value=180k
R53 "Res" R0402 2789.68,2006 r270 bottom value=2.7k
R54 "Res" R0402 2614.68,2013 r0 bottom value=15k
R55 "LRMAM1206-R02FT5" LRMA1206 1167.05,4860.77 r270 top net-tie value=0R02
R56 "Res" R0402 2632.68,2380 r180 bottom value=16k
R57 "Res" R0402 2754.68,2006 r90 bottom value=33k
R58 "Res" R0402 2614.68,1980 r180 bottom value=16k
R59 "Res" R0402 2604.31,1905.28 r0 top value=10.2k
R60 "Res" R0402 2526.68,1967 r270 top value=12.4k
R61 "Res" R0402 2529.31,1905.28 r0 top value=31.6k
R62 "LRMAM1206-R02FT5" LRMA1206 1782.76,1753 r180 top net-tie value=0R02
R63 "Res" R0402 2223.31,2160.28 r90 top value=22k
R64 "Res" R0402 2223.31,2244.28 r90 top value=22k
R65 "Res" R0402 2542.31,2427.28 r90 top value=7.87k
R66 "Res" R0402 2528,2500 r180 top value=7.5k
R67 "Res" R0402 2755.68,1967 r270 top value=5.9k
R68 "Res" R0402 2603,2499 r180 top value=30k
R69 "Res" R0402 2752.31,1905.28 r0 top value=20k
R70 "Res" R0402 2679.31,1905.28 r0 top value=16k
R71 "Res" R0402 2756.68,2426 r90 top value=5.9k
R72 "Res" R0402 3092.68,2186 r270 top value=8.87k
R73 "Res" R0402 3036.68,2208 r0 top value=10.2k
R74 "Res" R0402 2608.68,1983 r90 top value=43.2k
R75 "Res" R0402 2646.68,2421 r0 top value=10k
R76 "Res" R0402 3761,3854 r0 bottom value=2k
R77 "Res" R0402 3526,3857 r180 bottom value=28k
R78 "Res" R0402 3562.99,3799.21 r90 bottom value=20k
R79 "LRMAM1206-R02FT5" LRMA1206 1617,3431.9 r0 top net-tie value=0R02
R80 "Res" R0402 5203.29,4973.94 r90 top value=0
R81 "Res" R0603 4188,2437 r180 bottom value=39k
R82 "Res" R0402 1399,2894.9 r90 top value=4.99k
R83 "Res" R0603 4188,2387 r0 bottom value=15k
R84 "Res" R0603 3648,4534 r270 top value=47k
R85 "Res" R0603 3538,4424 r0 top value=47k
R86 "Res" R0603 3704,4378 r90 top value=1k
R87 "Res" R0603 3643,4350 r90 top value=47k
R88 "Res" R0603 3703,4506 r270 top value=10k
R89 "Res" R0603 3538,4474 r0 top value=10k
R90 "Res" R0603 3645,4844 r270 top value=47k
R91 "Res" R0603 3537,4736 r0 top value=47k
R92 "Res" R0603 3707,4696 r90 top value=1k
R93 "Res" R0603 3647,4672 r90 top value=47k
R94 "Res" R0603 3703,4818 r270 top value=10k
R95 "Res" R0603 3537,4783 r0 top value=10k
R96 "Res" R0402 4500,2905.51 r90 bottom value=47k
R97 "Res" R0402 5138,4975 r270 top value=0
R98 "Res" R0402 5236.43,4973.94 r90 top value=0
R99 "Res" R0402 5171.14,4975 r270 top value=0
R100 "Res" R0402 5335.86,4973.94 r90 top value=0
R101 "Res" R0402 5270.57,4975 r270 top value=0
R102 "Res" R0402 5369,4973.94 r90 top value=0
R103 "Res" R0402 5303.71,4975 r270 top value=0
R104 "Res" R0402 6100.29,4977.94 r90 top value=0
R105 "Res" R0402 6037,4979 r270 top value=0
R106 "Res" R0402 6132.43,4977.94 r90 top value=0
R107 "Res" R0402 6069.14,4979 r270 top value=0
R108 "Res" R0402 6228.86,4977.94 r90 top value=0
R109 "Res" R0402 6165.57,4979 r270 top value=0
R110 "Res" R0402 6261,4977.94 r90 top value=0
R111 "Res" R0402 6197.71,4979 r270 top value=0
Ren1 "Res" R0402 1201,2894.9 r90 top value=12.4k
Ren2 "Res" R0402 1237,2894.9 r90 top value=14.3k
Rf1 "Res" R0402 1492,2950.9 r0 top value=66.5k
Rf2 "Res" R0402 1470,2894.9 r90 top value=21k
Rin1 "Res" R0402 1274.05,4923.77 r270 top value=25R
Rin2 "Res" R0402 1878.76,1658 r180 top value=50R
Rin3 "Res" R0402 1549,3527.9 r90 top value=50R
Rout1 "Res" R0402 1329.05,4904.77 r0 top value=1k
Rout2 "Res" R0402 1861.76,1602 r270 top value=1k
Rout3 "Res" R0402 1549,3603.9 r90 top value=1k
Rt1 "Res" R0402 1318,2894.9 r90 top value=53.6k
S1 "SW DIP-4" SO8_N 5152,3895 r180 top
SFPCAGE1 "747540220" "SFPcage - dual" 3258,5596 r0 top locked (schematic designator SFPCage1)
SW1 "MFP106D" MFP106D 1640,5084 r270 top
U1 "S25FL128SAGMFI001" SOIC16 5195.51,3457 r180 bottom
U2 "XC7A35T-1FGG484C" FGG484 3915,3189 r0 top locked
U3 "PRTR5V0U4Y" SOT363 5195,4257 r90 bottom
U4 "24AA025E48T-I/OT" MCHP-SOT-23-OT6_N 4721.14,2798 r270 top
U5 "PRTR5V0U4Y" SOT363 5863,5163 r180 bottom
U6 "PRTR5V0U4Y" SOT363 5924,5108 r0 bottom
U7 "PRTR5V0U4Y" SOT363 6756,5158 r180 bottom
U8 "ADP5052" CP_48_13 2646.31,2196.28 r180 top value=Value
U9 "LT6106CS5" LT-S5-5-TSOT-23_N 1310.05,4801.77 r270 top
U10 "LT6106CS5" LT-S5-5-TSOT-23_N 1759.76,1620 r180 top
U11 "ADP123AUJZ-R7" ADI-UJ-5_N 3642,3856 r180 bottom
U12 "LT6106CS5" LT-S5-5-TSOT-23_N 1653,3584.9 r0 top
U13 "ADP2384ACPZN-R7" CP_24_12 1294,3061.9 r180 top value=Value
U14 "ADP1752ACPZ-1.0-R7" CP-16-4_N 4029.18,3916.8 r180 bottom
U15 "ADP123AUJZ-R7" ADI-UJ-5_N 4266,2529 r180 bottom
U16 "ADR127BUJZ-REEL7" ADI-UJ-6_N 3917,2494 r180 bottom
U17 "PRTR5V0U4Y" SOT363 5014,5120 r0 bottom

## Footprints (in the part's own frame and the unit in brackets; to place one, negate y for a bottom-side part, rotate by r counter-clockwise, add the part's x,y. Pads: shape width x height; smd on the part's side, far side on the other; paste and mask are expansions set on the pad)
1212-8dual [mm]
  rect 0.99x0.405 smd: 1(-1.435,0.99) 2(-1.435,0.33) 3(-1.435,-0.33) 4(-1.435,-0.99)
  rect 0.76x0.405 smd: 5(1.55,0.315) 5_1(1.55,0.945) 6(1.55,-0.315) 6_1(1.55,-0.945)
  rect 1.725x0.99 smd: 5_2(0.557,0.607) 6_2(0.557,-0.608)
  silkscreen extent -1.65,-1.65 1.65,1.65, body extent -1.65,-1.65 1.65,1.65, height 0.5
87831-1420 [mm] "Molex 2mm 14pin header"
  round 1 hole 1: 0(5,0)
  oct 1.3x1.3 hole 0.9: 1(-6,-1)
  round 1.3 hole 0.9: 2(-6,1) 3(-4,-1) 4(-4,1) 5(-2,-1) 6(-2,1) 7(0,-1) 8(0,1) 9(2,-1) 10(2,1) 11(4,-1) 12(4,1) 13(6,-1) 14(6,1)
  silkscreen extent -8.32,-3.15 8.32,3.15, body extent -8.35,-3.25 8.3,3.05, height 6.2
ADI-UJ-5_N [mm] "SOT23, 5-Leads, Body 2.9x1.6mm, Pitch 0.95mm, IPC Medium Density"
  rect 0.95x0.6 smd: 1(-1.225,0.95) 2(-1.225,0) 3(-1.225,-0.95) 4(1.225,-0.95) 5(1.225,0.95)
  silkscreen extent -1.35,-1.45 0.35,1.92, body extent -0.8,-1.45 0.8,1.45, height 1
ADI-UJ-6_N [mm] "SOT23, 6-Leads, Body 2.9x1.6mm, Pitch 0.95mm, IPC Medium Density"
  rect 0.95x0.6 smd: 1(-1.225,0.95) 2(-1.225,0) 3(-1.225,-0.95) 4(1.225,-0.95) 5(1.225,0) 6(1.225,0.95)
  silkscreen extent -1.35,-1.45 0.35,1.92, body extent -0.8,-1.45 0.8,1.45, height 1
ASMB-MTB0-0A3A2 [mm]
  rect 1.1x1.5 smd: 1(-0.75,-1.5) 2(-0.75,1.5) 3(0.75,1.5) 4(0.75,-1.5)
  silkscreen extent -1.78,-2.67 -0.25,-0.76, body extent -1.4,-1.68 1.4,1.82, height 1.9
ASP-134603-01 [mil]
  round 25 smd paste+5 mask+2: C1(975,-125) C2(925,-125) C3(875,-125) C4(825,-125) C5(775,-125) C6(725,-125) C7(675,-125) C8(625,-125) C9(575,-125) C10(525,-125) C11(475,-125) C12(425,-125) C13(375,-125) C14(325,-125) C15(275,-125) C16(225,-125) C17(175,-125) C18(125,-125) C19(75,-125) C20(25,-125) C21(-25,-125) C22(-75,-125) C23(-125,-125) C24(-175,-125) C25(-225,-125) C26(-275,-125) C27(-325,-125) C28(-375,-125) C29(-425,-125) C30(-475,-125) C31(-525,-125) C32(-575,-125) C33(-625,-125) C34(-675,-125) C35(-725,-125) C36(-775,-125) C37(-825,-125) C38(-875,-125) C39(-925,-125) C40(-975,-125) D1(975,-75) D2(925,-75) D3(875,-75) D4(825,-75) D5(775,-75) D6(725,-75) D7(675,-75) D8(625,-75) D9(575,-75) D10(525,-75) D11(475,-75) D12(425,-75) D13(375,-75) D14(325,-75) D15(275,-75) D16(225,-75) D17(175,-75) D18(125,-75) D19(75,-75) D20(25,-75) D21(-25,-75) D22(-75,-75) D23(-125,-75) D24(-175,-75) D25(-225,-75) D26(-275,-75) D27(-325,-75) D28(-375,-75) D29(-425,-75) D30(-475,-75) D31(-525,-75) D32(-575,-75) D33(-625,-75) D34(-675,-75) D35(-725,-75) D36(-775,-75) D37(-825,-75) D38(-875,-75) D39(-925,-75) D40(-975,-75) G1(975,75) G2(925,75) G3(875,75) G4(825,75) G5(775,75) G6(725,75) G7(675,75) G8(625,75) G9(575,75) G10(525,75) G11(475,75) G12(425,75) G13(375,75) G14(325,75) G15(275,75) G16(225,75) G17(175,75) G18(125,75) G19(75,75) G20(25,75) G21(-25,75) G22(-75,75) G23(-125,75) G24(-175,75) G25(-225,75) G26(-275,75) G27(-325,75) G28(-375,75) G29(-425,75) G30(-475,75) G31(-525,75) G32(-575,75) G33(-625,75) G34(-675,75) G35(-725,75) G36(-775,75) G37(-825,75) G38(-875,75) G39(-925,75) G40(-975,75) H1(975,125) H2(925,125) H3(875,125) H4(825,125) H5(775,125) H6(725,125) H7(675,125) H8(625,125) H9(575,125) H10(525,125) H11(475,125) H12(425,125) H13(375,125) H14(325,125) H15(275,125) H16(225,125) H17(175,125) H18(125,125) H19(75,125) H20(25,125) H21(-25,125) H22(-75,125) H23(-125,125) H24(-175,125) H25(-225,125) H26(-275,125) H27(-325,125) H28(-375,125) H29(-425,125) H30(-475,125) H31(-525,125) H32(-575,125) H33(-625,125) H34(-675,125) H35(-725,125) H36(-775,125) H37(-825,125) H38(-875,125) H39(-925,125) H40(-975,125)
  round 0 hole 50 unplated: MH1(1070.5,-120) MH2(-1070.5,0)
  silkscreen extent -1155,-280 1145,280, body extent -1131,-295 1151,283, height 259
B3S-1002 [mm]
  rrect15% 1.55x1.3 smd: 1(3.975,-2.25) 2(-3.975,-2.25) 3(3.975,2.25) 4(-3.975,2.25)
  silkscreen extent -3.1,-2.2 2.87,2.21, body extent -4.63,-3.33 4.37,3.27, height 4.4
C0402 [mm]
  rect 0.6x0.55 smd: 1(-0.425,0) 2(0.425,0)
  silkscreen extent -0.1,-0.3 0.1,0.3, body extent -0.54,-0.25 0.54,0.25, height 0.35
C0603 [mm]
  rect 0.6x1 smd: 1(-0.75,0) 2(0.75,0)
  silkscreen extent -0.28,-0.53 0.28,0.53, body extent -0.76,-0.44 0.76,0.44, height 0.35
C0805 [mm]
  rect 0.7x1.3 smd: 1(-0.95,0) 2(0.95,0)
  silkscreen extent -0.43,-0.69 0.43,0.69, body extent -1.02,-0.6 1.02,0.6, height 0.35
C1206 [mm]
  rect 0.9x1.7 smd: 1(-1.45,0) 2(1.45,0)
  silkscreen extent -2.06,-1 2.03,1, body extent -1.52,-0.76 1.52,0.76, height 0.55
C1206_P [mm]
  rect 1.1x1.7 smd: 1(-1.35,0) 2(1.35,0)
  silkscreen extent -2.29,-0.75 0.4,1.27, body extent -1.7,-0.9 1.7,0.9, height 1.3
C1210 [mm]
  rect 0.9x2.6 smd: 1(-1.45,0) 2(1.45,0)
  silkscreen extent -0.73,-1.24 0.74,1.27, body extent -1.52,-1.14 1.52,1.14, height 0.55
C7343 [mm]
  rect 2.5x2 smd: 1(-2,0) 2(2,0)
  silkscreen extent -0.51,-0.94 0.53,0.94
CP-16-4_N [mm] "QFN, 16-Leads, Body 4x4mm, Pitch 0.65mm, Thermal Pad 2.1x2.1mm, IPC Medium Density"
  oval 0.95x0.3 smd: 1(-1.875,0.975) 2(-1.875,0.325) 3(-1.875,-0.325) 4(-1.875,-0.975) 9(1.875,-0.975) 10(1.875,-0.325) 11(1.875,0.325) 12(1.875,0.975)
  oval 0.3x0.95 smd: 5(-0.975,-1.875) 6(-0.325,-1.875) 7(0.325,-1.875) 8(0.975,-1.875) 13(0.975,1.875) 14(0.325,1.875) 15(-0.325,1.875) 16(-0.975,1.875)
  rect 2.1x2.1 smd: 17(0,0)
  silkscreen extent -2.93,-2.15 2.15,2.15, body extent -2,-2 2,2, height 1
CP_24_12 [mm]
  rect 0.805x0.25 smd: 1(-1.952,1.25) 2(-1.952,0.75) 3(-1.952,0.25) 4(-1.952,-0.25) 5(-1.952,-0.75) 6(-1.952,-1.25) 13(1.952,-1.25) 14(1.952,-0.75) 15(1.952,-0.25) 16(1.952,0.25) 17(1.952,0.75) 18(1.952,1.25)
  rect 2.7x1.5 smd: 4_1(0,0.61)
  rect 0.25x0.805 smd: 7(-1.25,-1.952) 8(-0.75,-1.952) 9(-0.25,-1.952) 10(0.25,-1.952) 11(0.75,-1.952) 12(1.25,-1.952) 19(1.25,1.952) 20(0.75,1.952) 21(0.25,1.952) 22(-0.25,1.952) 23(-0.75,1.952) 24(-1.25,1.952)
  rect 2.7x1.05 smd: 14_1(0,-0.838)
  silkscreen extent -2.05,-2.86 2.05,2.86, body extent -2.03,-2.03 2.03,2.03, height 0.25
CP_48_13 [mm]
  rect 0.755x0.3 smd: 1(-3.433,2.75) 2(-3.433,2.25) 3(-3.433,1.75) 4(-3.433,1.25) 5(-3.433,0.75) 6(-3.433,0.25) 7(-3.433,-0.25) 8(-3.433,-0.75) 9(-3.433,-1.25) 10(-3.433,-1.75) 11(-3.433,-2.25) 12(-3.433,-2.75) 25(3.433,-2.75) 26(3.433,-2.25) 27(3.433,-1.75) 28(3.433,-1.25) 29(3.433,-0.75) 30(3.433,-0.25) 31(3.433,0.25) 32(3.433,0.75) 33(3.433,1.25) 34(3.433,1.75) 35(3.433,2.25) 36(3.433,2.75)
  rect 0.3x0.755 smd: 13(-2.75,-3.433) 14(-2.25,-3.433) 15(-1.75,-3.433) 16(-1.25,-3.433) 17(-0.75,-3.433) 18(-0.25,-3.433) 19(0.25,-3.433) 20(0.75,-3.433) 21(1.25,-3.433) 22(1.75,-3.433) 23(2.25,-3.433) 24(2.75,-3.433) 37(2.75,3.433) 38(2.25,3.433) 39(1.75,3.433) 40(1.25,3.433) 41(0.75,3.433) 42(0.25,3.433) 43(-0.25,3.433) 44(-0.75,3.433) 45(-1.25,3.433) 46(-1.75,3.433) 47(-2.25,3.433) 48(-2.75,3.433)
  rect 5.6x5.6 smd mask-2.781: 49(0,0)
  silkscreen extent -4.32,-4.32 4.32,4.32, body extent -3.43,-3.43 3.4,3.4, height 0.76
DR0608 [mil]
  round 60 hole 30: 1(-68.9,0) 2(68.9,0)
  silkscreen extent -147,-148 147,148, body extent -149,-146 147,150, height 382
DSC1123_32_25 [mm]
  rect 0.9x1 smd: 1(-1.075,-0.95) 3(1.075,-0.95) 4(1.075,0.95) 6(-1.075,0.95)
  rect 0.5x1 smd: 2(0,-0.95) 5(0,0.95)
  silkscreen extent -2.26,-1.5 1.78,1.4, body extent -1.78,-1.27 1.78,1.4, height 0.85
FGG484 [mm] "BGA, 484-Balls, Body 23x23mm, Pitch 1mm"
  round 0.5 smd: A1(-10.5,10.5) A2(-9.5,10.5) A3(-8.5,10.5) A4(-7.5,10.5) A5(-6.5,10.5) A6(-5.5,10.5) A7(-4.5,10.5) A8(-3.5,10.5) A9(-2.5,10.5) A10(-1.5,10.5) A11(-0.5,10.5) A12(0.5,10.5) A13(1.5,10.5) A14(2.5,10.5) A15(3.5,10.5) A16(4.5,10.5) A17(5.5,10.5) A18(6.5,10.5) A19(7.5,10.5) A20(8.5,10.5) A21(9.5,10.5) A22(10.5,10.5) AA1(-10.5,-9.5) AA2(-9.5,-9.5) AA3(-8.5,-9.5) AA4(-7.5,-9.5) AA5(-6.5,-9.5) AA6(-5.5,-9.5) AA7(-4.5,-9.5) AA8(-3.5,-9.5) AA9(-2.5,-9.5) AA10(-1.5,-9.5) AA11(-0.5,-9.5) AA12(0.5,-9.5) AA13(1.5,-9.5) AA14(2.5,-9.5) AA15(3.5,-9.5) AA16(4.5,-9.5) AA17(5.5,-9.5) AA18(6.5,-9.5) AA19(7.5,-9.5) AA20(8.5,-9.5) AA21(9.5,-9.5) AA22(10.5,-9.5) AB1(-10.5,-10.5) AB2(-9.5,-10.5) AB3(-8.5,-10.5) AB4(-7.5,-10.5) AB5(-6.5,-10.5) AB6(-5.5,-10.5) AB7(-4.5,-10.5) AB8(-3.5,-10.5) AB9(-2.5,-10.5) AB10(-1.5,-10.5) AB11(-0.5,-10.5) AB12(0.5,-10.5) AB13(1.5,-10.5) AB14(2.5,-10.5) AB15(3.5,-10.5) AB16(4.5,-10.5) AB17(5.5,-10.5) AB18(6.5,-10.5) AB19(7.5,-10.5) AB20(8.5,-10.5) AB21(9.5,-10.5) AB22(10.5,-10.5) B1(-10.5,9.5) B2(-9.5,9.5) B3(-8.5,9.5) B4(-7.5,9.5) B5(-6.5,9.5) B6(-5.5,9.5) B7(-4.5,9.5) B8(-3.5,9.5) B9(-2.5,9.5) B10(-1.5,9.5) B11(-0.5,9.5) B12(0.5,9.5) B13(1.5,9.5) B14(2.5,9.5) B15(3.5,9.5) B16(4.5,9.5) B17(5.5,9.5) B18(6.5,9.5) B19(7.5,9.5) B20(8.5,9.5) B21(9.5,9.5) B22(10.5,9.5) C1(-10.5,8.5) C2(-9.5,8.5) C3(-8.5,8.5) C4(-7.5,8.5) C5(-6.5,8.5) C6(-5.5,8.5) C7(-4.5,8.5) C8(-3.5,8.5) C9(-2.5,8.5) C10(-1.5,8.5) C11(-0.5,8.5) C12(0.5,8.5) C13(1.5,8.5) C14(2.5,8.5) C15(3.5,8.5) C16(4.5,8.5) C17(5.5,8.5) C18(6.5,8.5) C19(7.5,8.5) C20(8.5,8.5) C21(9.5,8.5) C22(10.5,8.5) D1(-10.5,7.5) D2(-9.5,7.5) D3(-8.5,7.5) D4(-7.5,7.5) D5(-6.5,7.5) D6(-5.5,7.5) D7(-4.5,7.5) D8(-3.5,7.5) D9(-2.5,7.5) D10(-1.5,7.5) D11(-0.5,7.5) D12(0.5,7.5) D13(1.5,7.5) D14(2.5,7.5) D15(3.5,7.5) D16(4.5,7.5) D17(5.5,7.5) D18(6.5,7.5) D19(7.5,7.5) D20(8.5,7.5) D21(9.5,7.5) D22(10.5,7.5) E1(-10.5,6.5) E2(-9.5,6.5) E3(-8.5,6.5) E4(-7.5,6.5) E5(-6.5,6.5) E6(-5.5,6.5) E7(-4.5,6.5) E8(-3.5,6.5) E9(-2.5,6.5) E10(-1.5,6.5) E11(-0.5,6.5) E12(0.5,6.5) E13(1.5,6.5) E14(2.5,6.5) E15(3.5,6.5) E16(4.5,6.5) E17(5.5,6.5) E18(6.5,6.5) E19(7.5,6.5) E20(8.5,6.5) E21(9.5,6.5) E22(10.5,6.5) F1(-10.5,5.5) F2(-9.5,5.5) F3(-8.5,5.5) F4(-7.5,5.5) F5(-6.5,5.5) F6(-5.5,5.5) F7(-4.5,5.5) F8(-3.5,5.5) F9(-2.5,5.5) F10(-1.5,5.5) F11(-0.5,5.5) F12(0.5,5.5) F13(1.5,5.5) F14(2.5,5.5) F15(3.5,5.5) F16(4.5,5.5) F17(5.5,5.5) F18(6.5,5.5) F19(7.5,5.5) F20(8.5,5.5) F21(9.5,5.5) F22(10.5,5.5) G1(-10.5,4.5) G2(-9.5,4.5) G3(-8.5,4.5) G4(-7.5,4.5) G5(-6.5,4.5) G6(-5.5,4.5) G7(-4.5,4.5) G8(-3.5,4.5) G9(-2.5,4.5) G10(-1.5,4.5) G11(-0.5,4.5) G12(0.5,4.5) G13(1.5,4.5) G14(2.5,4.5) G15(3.5,4.5) G16(4.5,4.5) G17(5.5,4.5) G18(6.5,4.5) G19(7.5,4.5) G20(8.5,4.5) G21(9.5,4.5) G22(10.5,4.5) H1(-10.5,3.5) H2(-9.5,3.5) H3(-8.5,3.5) H4(-7.5,3.5) H5(-6.5,3.5) H6(-5.5,3.5) H7(-4.5,3.5) H8(-3.5,3.5) H9(-2.5,3.5) H10(-1.5,3.5) H11(-0.5,3.5) H12(0.5,3.5) H13(1.5,3.5) H14(2.5,3.5) H15(3.5,3.5) H16(4.5,3.5) H17(5.5,3.5) H18(6.5,3.5) H19(7.5,3.5) H20(8.5,3.5) H21(9.5,3.5) H22(10.5,3.5) J1(-10.5,2.5) J2(-9.5,2.5) J3(-8.5,2.5) J4(-7.5,2.5) J5(-6.5,2.5) J6(-5.5,2.5) J7(-4.5,2.5) J8(-3.5,2.5) J9(-2.5,2.5) J10(-1.5,2.5) J11(-0.5,2.5) J12(0.5,2.5) J13(1.5,2.5) J14(2.5,2.5) J15(3.5,2.5) J16(4.5,2.5) J17(5.5,2.5) J18(6.5,2.5) J19(7.5,2.5) J20(8.5,2.5) J21(9.5,2.5) J22(10.5,2.5) K1(-10.5,1.5) K2(-9.5,1.5) K3(-8.5,1.5) K4(-7.5,1.5) K5(-6.5,1.5) K6(-5.5,1.5) K7(-4.5,1.5) K8(-3.5,1.5) K9(-2.5,1.5) K10(-1.5,1.5) K11(-0.5,1.5) K12(0.5,1.5) K13(1.5,1.5) K14(2.5,1.5) K15(3.5,1.5) K16(4.5,1.5) K17(5.5,1.5) K18(6.5,1.5) K19(7.5,1.5) K20(8.5,1.5) K21(9.5,1.5) K22(10.5,1.5) L1(-10.5,0.5) L2(-9.5,0.5) L3(-8.5,0.5) L4(-7.5,0.5) L5(-6.5,0.5) L6(-5.5,0.5) L7(-4.5,0.5) L8(-3.5,0.5) L9(-2.5,0.5) L10(-1.5,0.5) L11(-0.5,0.5) L12(0.5,0.5) L13(1.5,0.5) L14(2.5,0.5) L15(3.5,0.5) L16(4.5,0.5) L17(5.5,0.5) L18(6.5,0.5) L19(7.5,0.5) L20(8.5,0.5) L21(9.5,0.5) L22(10.5,0.5) M1(-10.5,-0.5) M2(-9.5,-0.5) M3(-8.5,-0.5) M4(-7.5,-0.5) M5(-6.5,-0.5) M6(-5.5,-0.5) M7(-4.5,-0.5) M8(-3.5,-0.5) M9(-2.5,-0.5) M10(-1.5,-0.5) M11(-0.5,-0.5) M12(0.5,-0.5) M13(1.5,-0.5) M14(2.5,-0.5) M15(3.5,-0.5) M16(4.5,-0.5) M17(5.5,-0.5) M18(6.5,-0.5) M19(7.5,-0.5) M20(8.5,-0.5) M21(9.5,-0.5) M22(10.5,-0.5) N1(-10.5,-1.5) N2(-9.5,-1.5) N3(-8.5,-1.5) N4(-7.5,-1.5) N5(-6.5,-1.5) N6(-5.5,-1.5) N7(-4.5,-1.5) N8(-3.5,-1.5) N9(-2.5,-1.5) N10(-1.5,-1.5) N11(-0.5,-1.5) N12(0.5,-1.5) N13(1.5,-1.5) N14(2.5,-1.5) N15(3.5,-1.5) N16(4.5,-1.5) N17(5.5,-1.5) N18(6.5,-1.5) N19(7.5,-1.5) N20(8.5,-1.5) N21(9.5,-1.5) N22(10.5,-1.5) P1(-10.5,-2.5) P2(-9.5,-2.5) P3(-8.5,-2.5) P4(-7.5,-2.5) P5(-6.5,-2.5) P6(-5.5,-2.5) P7(-4.5,-2.5) P8(-3.5,-2.5) P9(-2.5,-2.5) P10(-1.5,-2.5) P11(-0.5,-2.5) P12(0.5,-2.5) P13(1.5,-2.5) P14(2.5,-2.5) P15(3.5,-2.5) P16(4.5,-2.5) P17(5.5,-2.5) P18(6.5,-2.5) P19(7.5,-2.5) P20(8.5,-2.5) P21(9.5,-2.5) P22(10.5,-2.5) R1(-10.5,-3.5) R2(-9.5,-3.5) R3(-8.5,-3.5) R4(-7.5,-3.5) R5(-6.5,-3.5) R6(-5.5,-3.5) R7(-4.5,-3.5) R8(-3.5,-3.5) R9(-2.5,-3.5) R10(-1.5,-3.5) R11(-0.5,-3.5) R12(0.5,-3.5) R13(1.5,-3.5) R14(2.5,-3.5) R15(3.5,-3.5) R16(4.5,-3.5) R17(5.5,-3.5) R18(6.5,-3.5) R19(7.5,-3.5) R20(8.5,-3.5) R21(9.5,-3.5) R22(10.5,-3.5) T1(-10.5,-4.5) T2(-9.5,-4.5) T3(-8.5,-4.5) T4(-7.5,-4.5) T5(-6.5,-4.5) T6(-5.5,-4.5) T7(-4.5,-4.5) T8(-3.5,-4.5) T9(-2.5,-4.5) T10(-1.5,-4.5) T11(-0.5,-4.5) T12(0.5,-4.5) T13(1.5,-4.5) T14(2.5,-4.5) T15(3.5,-4.5) T16(4.5,-4.5) T17(5.5,-4.5) T18(6.5,-4.5) T19(7.5,-4.5) T20(8.5,-4.5) T21(9.5,-4.5) T22(10.5,-4.5) U1(-10.5,-5.5) U2(-9.5,-5.5) U3(-8.5,-5.5) U4(-7.5,-5.5) U5(-6.5,-5.5) U6(-5.5,-5.5) U7(-4.5,-5.5) U8(-3.5,-5.5) U9(-2.5,-5.5) U10(-1.5,-5.5) U11(-0.5,-5.5) U12(0.5,-5.5) U13(1.5,-5.5) U14(2.5,-5.5) U15(3.5,-5.5) U16(4.5,-5.5) U17(5.5,-5.5) U18(6.5,-5.5) U19(7.5,-5.5) U20(8.5,-5.5) U21(9.5,-5.5) U22(10.5,-5.5) V1(-10.5,-6.5) V2(-9.5,-6.5) V3(-8.5,-6.5) V4(-7.5,-6.5) V5(-6.5,-6.5) V6(-5.5,-6.5) V7(-4.5,-6.5) V8(-3.5,-6.5) V9(-2.5,-6.5) V10(-1.5,-6.5) V11(-0.5,-6.5) V12(0.5,-6.5) V13(1.5,-6.5) V14(2.5,-6.5) V15(3.5,-6.5) V16(4.5,-6.5) V17(5.5,-6.5) V18(6.5,-6.5) V19(7.5,-6.5) V20(8.5,-6.5) V21(9.5,-6.5) V22(10.5,-6.5) W1(-10.5,-7.5) W2(-9.5,-7.5) W3(-8.5,-7.5) W4(-7.5,-7.5) W5(-6.5,-7.5) W6(-5.5,-7.5) W7(-4.5,-7.5) W8(-3.5,-7.5) W9(-2.5,-7.5) W10(-1.5,-7.5) W11(-0.5,-7.5) W12(0.5,-7.5) W13(1.5,-7.5) W14(2.5,-7.5) W15(3.5,-7.5) W16(4.5,-7.5) W17(5.5,-7.5) W18(6.5,-7.5) W19(7.5,-7.5) W20(8.5,-7.5) W21(9.5,-7.5) W22(10.5,-7.5) Y1(-10.5,-8.5) Y2(-9.5,-8.5) Y3(-8.5,-8.5) Y4(-7.5,-8.5) Y5(-6.5,-8.5) Y6(-5.5,-8.5) Y7(-4.5,-8.5) Y8(-3.5,-8.5) Y9(-2.5,-8.5) Y10(-1.5,-8.5) Y11(-0.5,-8.5) Y12(0.5,-8.5) Y13(1.5,-8.5) Y14(2.5,-8.5) Y15(3.5,-8.5) Y16(4.5,-8.5) Y17(5.5,-8.5) Y18(6.5,-8.5) Y19(7.5,-8.5) Y20(8.5,-8.5) Y21(9.5,-8.5) Y22(10.5,-8.5)
  silkscreen extent -12.27,-11.5 11.5,11.5, body extent -11.5,-11.5 11.5,11.5, height 2.6
HDR1X2 [mm] "Connector; Header; 2 Position"
  rect 1.5x1.5 hole 0.9: 1(0,0)
  round 1.5 hole 0.9: 2(2.54,0)
  silkscreen extent -1.27,-1.27 3.81,1.27
HDR2X6 [mm] "Connector; Header; 6x2 Position"
  rect 1.5x1.5 hole 0.9: 1(0,0)
  round 1.5 hole 0.9: 2(0,2.54) 3(2.54,0) 4(2.54,2.54) 5(5.08,0) 6(5.08,2.54) 7(7.62,0) 8(7.62,2.54) 9(10.16,0) 10(10.16,2.54) 11(12.7,0) 12(12.7,2.54)
  silkscreen extent -1.27,-1.27 13.97,3.81
KLD2020 [mm] "DC Power Jack, 2.5mm, KLD Series, PCB Mount"
  rect 1.651x4.064 hole 1 slot 3.175 at 90 deg: 1(13.6,2.4) 2(7.8,2.4)
  rect 4.064x1.651 hole 1 slot 3.1 at 0 deg: 3(10.6,-2.4)
  silkscreen extent 0,-2.4 14.5,6.6, body extent 0.08,-2.49 14.58,7.01, height 10.94
KP-1608QBC-D [mm]
  rect 0.8x0.8 smd: 1(-0.825,0) 2(0.825,0)
  silkscreen extent -0.22,-0.44 0.24,0.47
LRMA1206 [mil]
  rect 66.93x70.87 smd: 1(-64.96,0) 2(64.96,0)
  rect 10x10 smd: 3(-18,0) 4(18,0)
  Component Side lines w10: 63.96,0 18,0 ; -18,0 -64.96,0
LT-S5-5-TSOT-23_N [mm] "SOT23, 5-Leads, Body 2.90x1.63mm, Pitch 0.95mm, IPC Medium Density"
  rect 1.3x0.55 smd: 1(-1.2,0.95) 2(-1.2,0) 3(-1.2,-0.95) 4(1.2,-0.95) 5(1.2,0.95)
  silkscreen extent -1.32,-1.45 0.15,1.9, body extent -0.87,-1.45 0.87,1.45, height 1
MCHP-SOT-23-OT6_N [mm] "SOT23, 6-Leads, Body 2.9x1.55mm, Pitch 0.95mm, IPC Medium Density"
  rect 1.1x0.6 smd: 1(-1.2,0.95) 2(-1.2,0) 3(-1.2,-0.95) 4(1.2,-0.95) 5(1.2,0) 6(1.2,0.95)
  silkscreen extent -1.32,-1.55 0.25,1.93, body extent -0.9,-1.55 0.9,1.55, height 1.45
MFP106D [mm]
  round 2.7 hole 1.85: 1(-4.6,0) 2(0,0) 3(4.6,0)
  silkscreen extent -6.5,-3.5 6.5,3.5
MSS1048 [mm]
  rect 3.56x1.78 smd: 1(0,4.7) 2(0,-4.7)
  body extent -5.23,-5.15 4.97,5.15, height 5
PMOD_12 [mil]
  rect 60x60 hole 30: 1(-50,250)
  round 60 hole 30: 2(-50,150) 3(-50,50) 4(-50,-50) 5(-50,-150) 6(-50,-250) 7(50,250) 8(50,150) 9(50,50) 10(50,-50) 11(50,-150) 12(50,-250)
  silkscreen extent -112,-300 450,300, body extent -48,-306 448,304, height 198
R0402 [mm]
  rect 0.6x0.55 smd: 1(-0.425,0) 2(0.452,0)
  silkscreen extent -0.1,-0.41 0.1,0.38, body extent -0.54,-0.25 0.54,0.25, height 0.35
R0603 [mm]
  rect 0.6x1 smd: 1(-0.75,0) 2(0.75,0)
  silkscreen extent -0.28,-0.53 0.28,0.53, body extent -0.76,-0.44 0.76,0.44, height 0.35
SFP+20 [mm]
  rect 0.5x2 smd: 1(1.4,-4.1) 2(2.2,-4.1) 3(3,-4.1) 4(3.8,-4.1) 5(4.6,-4.1) 6(5.4,-4.1) 7(6.2,-4.1) 8(7,-4.1) 9(7.8,-4.1) 10(8.6,-4.1) 11(8.2,4.1) 12(7.4,4.1) 13(6.6,4.1) 14(5.8,4.1) 15(5,4.1) 16(4.2,4.1) 17(3.4,4.1) 18(2.6,4.1) 19(1.8,4.1) 20(1,4.1)
  round 1.55 hole 1.55 paste+0 mask+0: _1(0,0) ""(9.6,0)
  silkscreen extent -0.7,-3.98 10.3,4.25, body extent -0.78,-4.46 10.22,4.69, height 5.37
"SFPcage - dual" [mm]
  round 0.95 hole 0.95: 0(-2.33,-41.6) 0_1(-7.13,-41.6) 0_2(-21.38,-41.6) 0_3(-16.58,-41.6) 0_4(0,-27.3) 0_5(-28.5,-27.3)
  rect 2x2 hole 1.05: 1(-28.5,-9.5) 2(-28.5,-19.5) 3(-28.5,-29.5) 4(-28.5,-39.5) 9(0,-4.5) 10(0,-14.5) 11(0,-24.5)
  rect 2x2 hole 0.95: 5(-14.25,-9.5) 6(-14.25,-19.5) 7(-14.25,-29.5) 8(-14.25,-39.5) 12(0,-32) 13(0,-37)
  rect 11.8x2 smd: 14(-7.125,-22.6) 15(-21.375,-22.6)
  Component Side keep-out region: -1,-42.3 1,-42.3 1,-38.202 -1,-38.202
  Component Side keep-out region: -1,-35.814 1,-35.814 1,-33.198 -1,-33.198
  Component Side keep-out region: -1,-30.81 1,-30.81 1,-25.679 -1,-25.679
  Component Side keep-out region: -1,-23.292 1,-23.292 1,-15.697 -1,-15.697
  Component Side keep-out region: -1,-13.31 1,-13.31 1,-5.69 -1,-5.69
  Component Side keep-out region: -29.5,-42.3 -27.5,-42.3 -27.5,-40.665 -29.5,-40.665
  Component Side keep-out region: -29.5,-28.296 -27.5,-28.296 -27.5,-20.701 -29.5,-20.701
  Component Side keep-out region: -29.5,-18.313 -27.5,-18.313 -27.5,-10.693 -29.5,-10.693
  Component Side keep-out region: -29.5,-38.303 -27.5,-38.303 -27.5,-30.683 -29.5,-30.683
  Component Side keep-out region: -29.5,-8.306 -27.5,-8.306 -27.5,0 -29.5,0
  Component Side keep-out region: -29.5,-1.803 1.016,-1.803 1.016,0 -29.5,0
  Component Side keep-out region: -1,-3.302 1,-3.302 1,0 -1,0
  Component Side keep-out region: -15.25,-8.306 -13.25,-8.306 -13.25,0 -15.25,0
  Component Side keep-out region: -18.13,-42.3 -13.25,-42.3 -13.25,-41.3 -18.13,-41.3
  Component Side keep-out region: -29.5,-42.3 -24.62,-42.3 -24.62,-41.3 -29.5,-41.3
  Component Side keep-out region: -3.88,-42.3 1,-42.3 1,-41.3 -3.88,-41.3
  Component Side keep-out region: -15.25,-42.3 -10.37,-42.3 -10.37,-41.3 -15.25,-41.3
  Component Side keep-out region: -15.25,-38.303 -13.25,-38.303 -13.25,-30.683 -15.25,-30.683
  Component Side keep-out region: -15.25,-18.313 -13.25,-18.313 -13.25,-10.693 -15.25,-10.693
  Component Side keep-out region: -15.25,-28.296 -13.25,-28.296 -13.25,-20.701 -15.25,-20.701
  Component Side keep-out region: -15.25,-42.3 -13.25,-42.3 -13.25,-40.665 -15.25,-40.665
  silkscreen extent -29.5,-42.3 1,0, body extent -29.09,-42.37 1.05,6.66, height 10.47
SO8_N [mm] "SOIC, 8-Leads, Body 4.9x3.9mm, Pitch 1.27mm, IPC Medium Density"
  oval 2.2x0.6 smd: 1(-2.4,1.905) 2(-2.4,0.635) 3(-2.4,-0.635) 4(-2.4,-1.905) 5(2.4,-1.905) 6(2.4,-0.635) 7(2.4,0.635) 8(2.4,1.905)
  silkscreen extent -2.53,-2.5 0.9,2.88, body extent -2,-2.5 2,2.5, height 1.75
SOD-123 [mm]
  rect 0.91x1.22 smd: 1(-1.635,0) 2(1.635,0)
  silkscreen extent -2.41,-1.02 2.41,1.02, body extent -1.65,-0.64 1.65,0.64, height 1.18
SOIC16 [mm]
  rect 2x0.6 smd: 1(0,0)
  oval 2x0.6 smd: 2(0,-1.27) 3(0,-2.54) 4(0,-3.81) 5(0,-5.08) 6(0,-6.35) 7(0,-7.62) 8(0,-8.89) 9(10.3,-8.89) 10(10.3,-7.62) 11(10.3,-6.35) 12(10.3,-5.08) 13(10.3,-3.81) 14(10.3,-2.54) 15(10.3,-1.27) 16(10.3,0)
  silkscreen extent 1.35,-9.53 8.89,0.63, body extent 1.35,-9.53 8.89,0.63, height 1
SOT363 [mm]
  oval 0.6x0.42 smd: 1(0,0)
  rect 0.6x0.42 smd: 2(0,-0.62) 3(0,-1.24) 4(1.9,-1.24) 5(1.9,-0.62) 6(1.9,0)
  silkscreen extent 0.38,-1.55 1.52,0.31
SOT-563 [mm]
  rect 0.343x0.45 smd: 1(-0.5,-0.625) 2(0,-0.625) 3(0.5,-0.625) 4(0.5,0.625) 5(0,0.625) 6(-0.5,0.625)
  silkscreen extent -1.07,-0.81 0.75,0.65, body extent -0.76,-0.64 0.76,0.64, height 0.45
SRP2512 [mm]
  rect 0.8x2 smd: 1(-1,0) 2(1,0)
  silkscreen extent -0.41,-1.02 0.43,1.02

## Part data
B1 B2: library part TS42
C1 C2 C3 C4 C5 C6 C7 C8 C9 C10 C11 C12 C13 C14 C15 C24 C25 C26 C27 C28 C29 C30 C31 C32 C33 C34 C35 C36 C37 C38 C39 C40 C41 C42 C43 C44 C45 C46 C47 C48 C49 C50 C51 C52 C53 C54 C55 C56 C57 C58 C59 C60 C61 C62 C63 C64 C65 C66 C67 C68 C69 C70 C71 C74 C75 C78 C79 C84 C85 C87 C89 C90 C94 C95 C96 C97 C105 C119 C120 C122 C123 C125 C126 C128 C129 Cout1 Cout2: "Capacitor"
C72 C73 C76 C77 C80 C81 C82 C83 C86 C91 C92 C93 C98 C99 C100 C101 C102 C103 C106 C107 C108 C109 C110 C111 C112 C113 C114 C115 C116 C117 C130: library part Cap, "Capacitor"
C88: library part "Cap Pol3", "Polarized Capacitor (Surface Mount)"
C118 C121 C124 C127: library part "Cap Pol", "Polarized Capacitor (Surface Mount)"
D1 D4 D5 D6 D7: library part LED
D2 D3: library part LED_RGB, "Typical INFRARED GaAs LED"
IC1 IC2: library part DSC1123, "Standard Clock Oscillators Oscillator Hi Perf -20C-70C 50ppm"
J1: "0.050\" PITCH SOCKET ARRAY ASSEMBLY.", Manufacturer=SAMTEC
J2: "Low Voltage Power Supply Connector"
J3 J4: library part SFP+
L1 L2 L3 L4 L5 L6 L7 L8: library part Inductor, "Inductor"
P1: library part "Header 2", "Header, 2-Pin"
P2: library part "Header 7X2", "Header, 7-Pin, Dual row"
P3 P4: library part "Header 6X2A", "Header, 6-Pin, Dual row"
P5: library part "Header 6X2", "Header, 6-Pin, Dual row"
P6: "Header, 2-Pin"
Q1: library part EM6K6
R1 R2 R3 R4 R5 R6 R7 R8 R9 R10 R11 R12 R13 R14 R15 R16 R17 R18 R19 R20 R21 R22 R23 R24 R25 R26 R27 R28 R29 R30 R31 R32 R33 R34 R35 R36 R38 R39 R40 R41 R42 R43 R44 R45 R46 R47 R48 R49 R50 R51 R52 R53 R54 R56 R57 R58 R60 R63 R64 R65 R67 R71 R74 R75 R76 R80 R84 R85 R86 R87 R88 R89 R90 R91 R92 R93 R94 R95 R96 R97 R98 R99 R100 R101 R102 R103 R104 R105 R106 R107 R108 R109 R110 R111 Ren1 Ren2 Rt1: "Resistor"
R37 R59 R61 R66 R68 R69 R70 R72 R73 R77 R78 R81 R82 R83 Rf1 Rf2 Rin1 Rin2 Rin3 Rout1 Rout2 Rout3: "Resistor", Tolerance=1%
R55 R62 R79: library part Res_sense, "Resistor"
S1: "DIP Switch, 4 Position, SPST"
SFPCAGE1: library part SFPcagedual
SW1: library part SW-SPDT, "SPDT Subminiature Toggle Switch, Right Angle Mounting, Vertical Actuation"
U2: "Artix-7 FPGA, 250 User I/Os, 4 GTP, 484-Ball BGA, Speed Grade 1, Commercial Grade, Pb-Free", Manufacturer=Xilinx, Operating Temperature Range=Commercial
U4: "2K bits I2C™ Serial EEPROM with EUI-48™ Node Identity, 1.7 to 5.5 V, 400 kHz, -40 to 85 degC, 6-pin SOT-23 (OT6), Tape and Reel", Manufacturer=Microchip, Supplier Part Number 1=24AA025E48T-I/OTTR-ND
U8: library part ADP5052ACPZ-R7, "Imported"
U9 U10 U12: "Single Channel, Low Cost, High Side Current Sense Operational Amplifier, 0.2 MHz Typical GBW, 5-Pin SOT-23 (S5-5), Commercial", Linear Technology Part Number=LT6106, Manufacturer="Linear Technology"
U11 U15: "300 mA, Low Quiescent Current, CMOS Linear Regulator, 2.3 to 5.5 V Vin, 0.8 to 5 V Vout, Industrial, 5-pin SOT23 (UJ-5), Reel", Manufacturer="Analog Devices", Supplier Part Number 1=ADP123AUJZ-R7TR-ND, Supply Current IGND @ Small Load=45uA
U13: "Imported"
U14: "0.8 A, Low VIN, Low Dropout Linear Regulator, 1.6 to 3.6 V Vin, 1 V Vout, Industrial, 16-pin QFN (CP-16-4), Reel", Manufacturer="Analog Devices", Preset Vout Values (V)=1, Supplier Part Number 1=ADP1752ACPZ-1.0-R7TR-ND, Supply Current IGND @ Small Load=90uA
U16: "Precision, Micropower LDO Voltage Reference in TSOT, 1.25 V Output, 2.7 to 18 V Supply, Industrial, 6-pin SOT23 (UJ-6), Reel", Manufacturer="Analog Devices", Operating Temp Range="-40 to 125 degC", Supplier Part Number 1=ADR127BUJZ-REEL7TR-ND

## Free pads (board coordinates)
  round 196.85 hole 125.98: 2(4446,5168)
  round 125.98 hole 106.3: MH3(801,1537) MH3(801,5487) MH3(6551.18,2121.68) MH3(6551.18,4602) MH3(6901,1537) MH3(6901,5487)

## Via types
v1: diameter 16, hole 8, Component Side to Bottom Side, tented both sides, 374 vias
v2: diameter 20, hole 10, Component Side to Bottom Side, 243 vias
v3: diameter 16, hole 8, Component Side to Bottom Side, 222 vias
v4: diameter 15, hole 7, Component Side to Bottom Side, 58 vias
v5: diameter 25, hole 10, Component Side to Bottom Side, 20 vias
v6: diameter 19.68, hole 7.87, Component Side to Bottom Side, 4 vias
v7: diameter 20, hole 10, Component Side to Bottom Side, tented both sides, 1 vias

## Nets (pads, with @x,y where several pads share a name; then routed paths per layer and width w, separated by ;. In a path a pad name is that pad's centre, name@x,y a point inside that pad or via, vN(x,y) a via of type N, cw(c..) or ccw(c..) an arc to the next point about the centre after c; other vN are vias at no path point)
3V3_I_MON: Rout2.2 U2.H14 U10.1 | length 4090.3
  Component Side w6: U2.H14@4013.43,3326.8 v1@4031.22,3309
  Component Side w12: U10.1@1807,1582.6 Rout2.2@1861.47,1582.6 ; Rout2.2@1861.76,1584.2 v2(1896.8,1584.2)
  Bottom Side w6: v2(1896.8,1584.2) 1820.8,1584.2 1776,1629 1776,2810 2332,3366 2801,3366 2852,3315 3154,3315 3303.57,3464.57 3436.43,3464.57 3500,3401 3634,3401 3634.68,3400.32 3648.77,3400.32 3649.45,3401 3858.99,3401 3864.99,3395 3902.16,3395 3905.16,3398 3912.01,3398 3921.24,3398 3958.1,3398 3969.1,3387 3984.72,3387 4015.75,3355.97 4015.75,3326.25 v1(4033,3309)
